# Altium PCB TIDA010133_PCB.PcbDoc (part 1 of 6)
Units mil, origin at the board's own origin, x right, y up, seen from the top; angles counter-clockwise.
Board outline 4100 x 6400 mil, 8 copper layers (Top Layer, Ground 1, Signal 1, Power 1, Ground 2, Signal 2, Power 2, Bottom Layer), stack 60.4 mil thick; 587 components, 322 nets, 1661 pads, 859 vias.
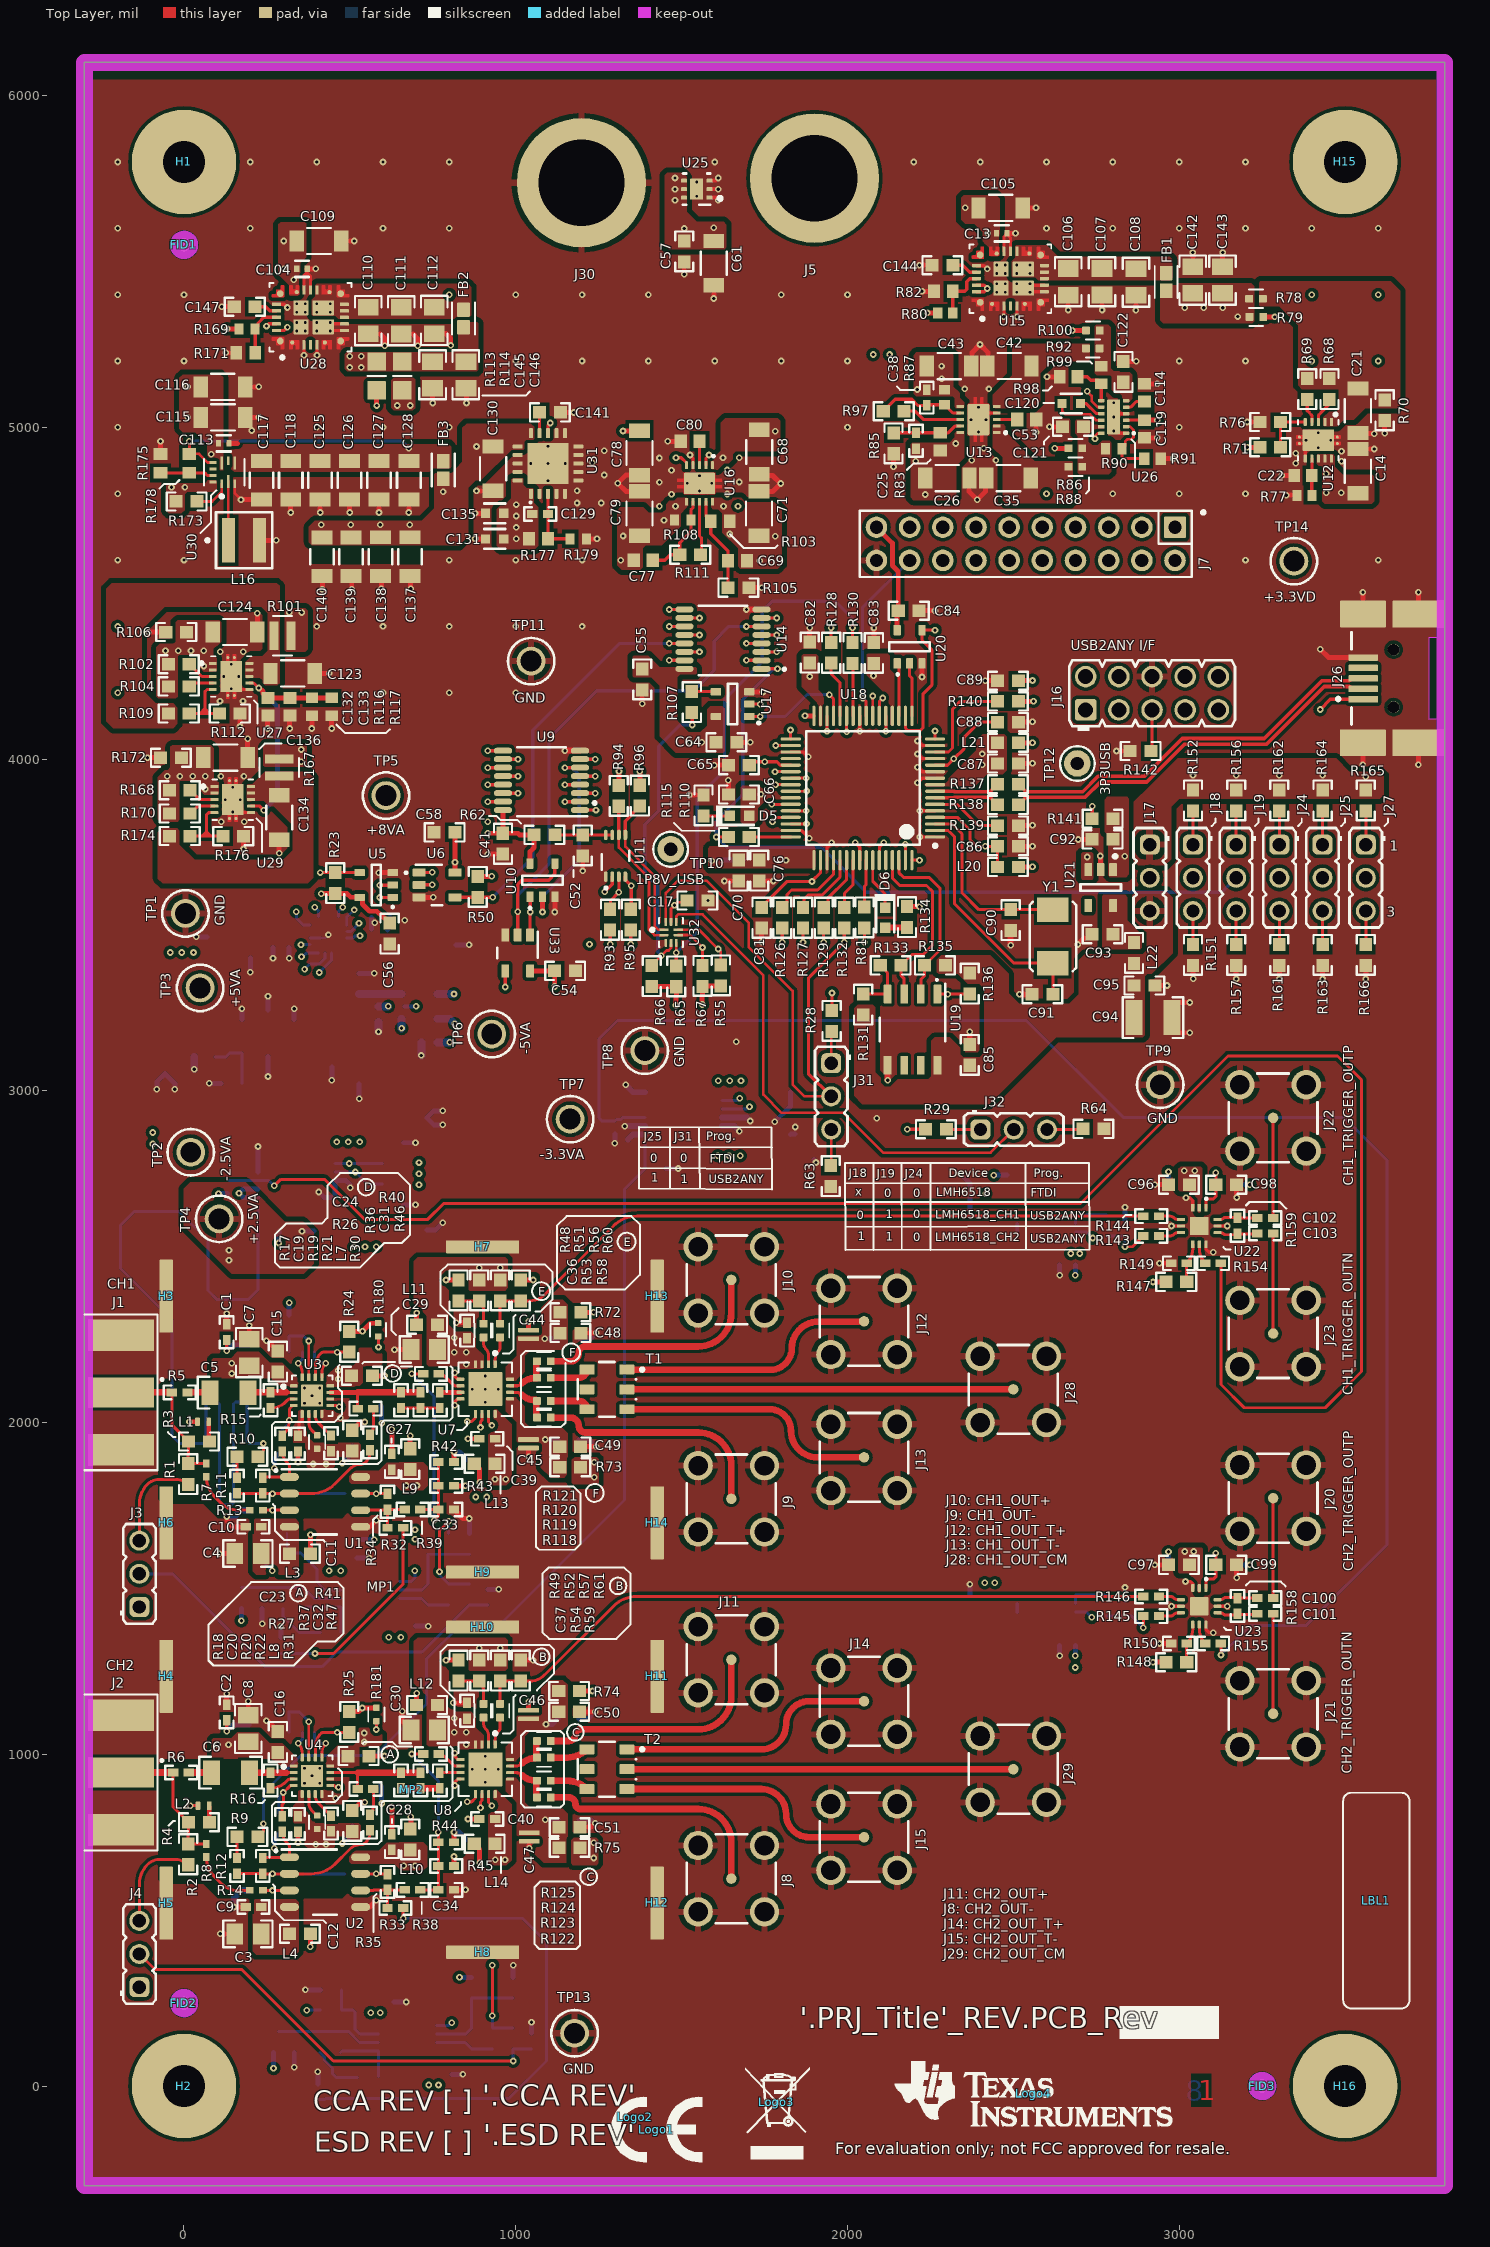
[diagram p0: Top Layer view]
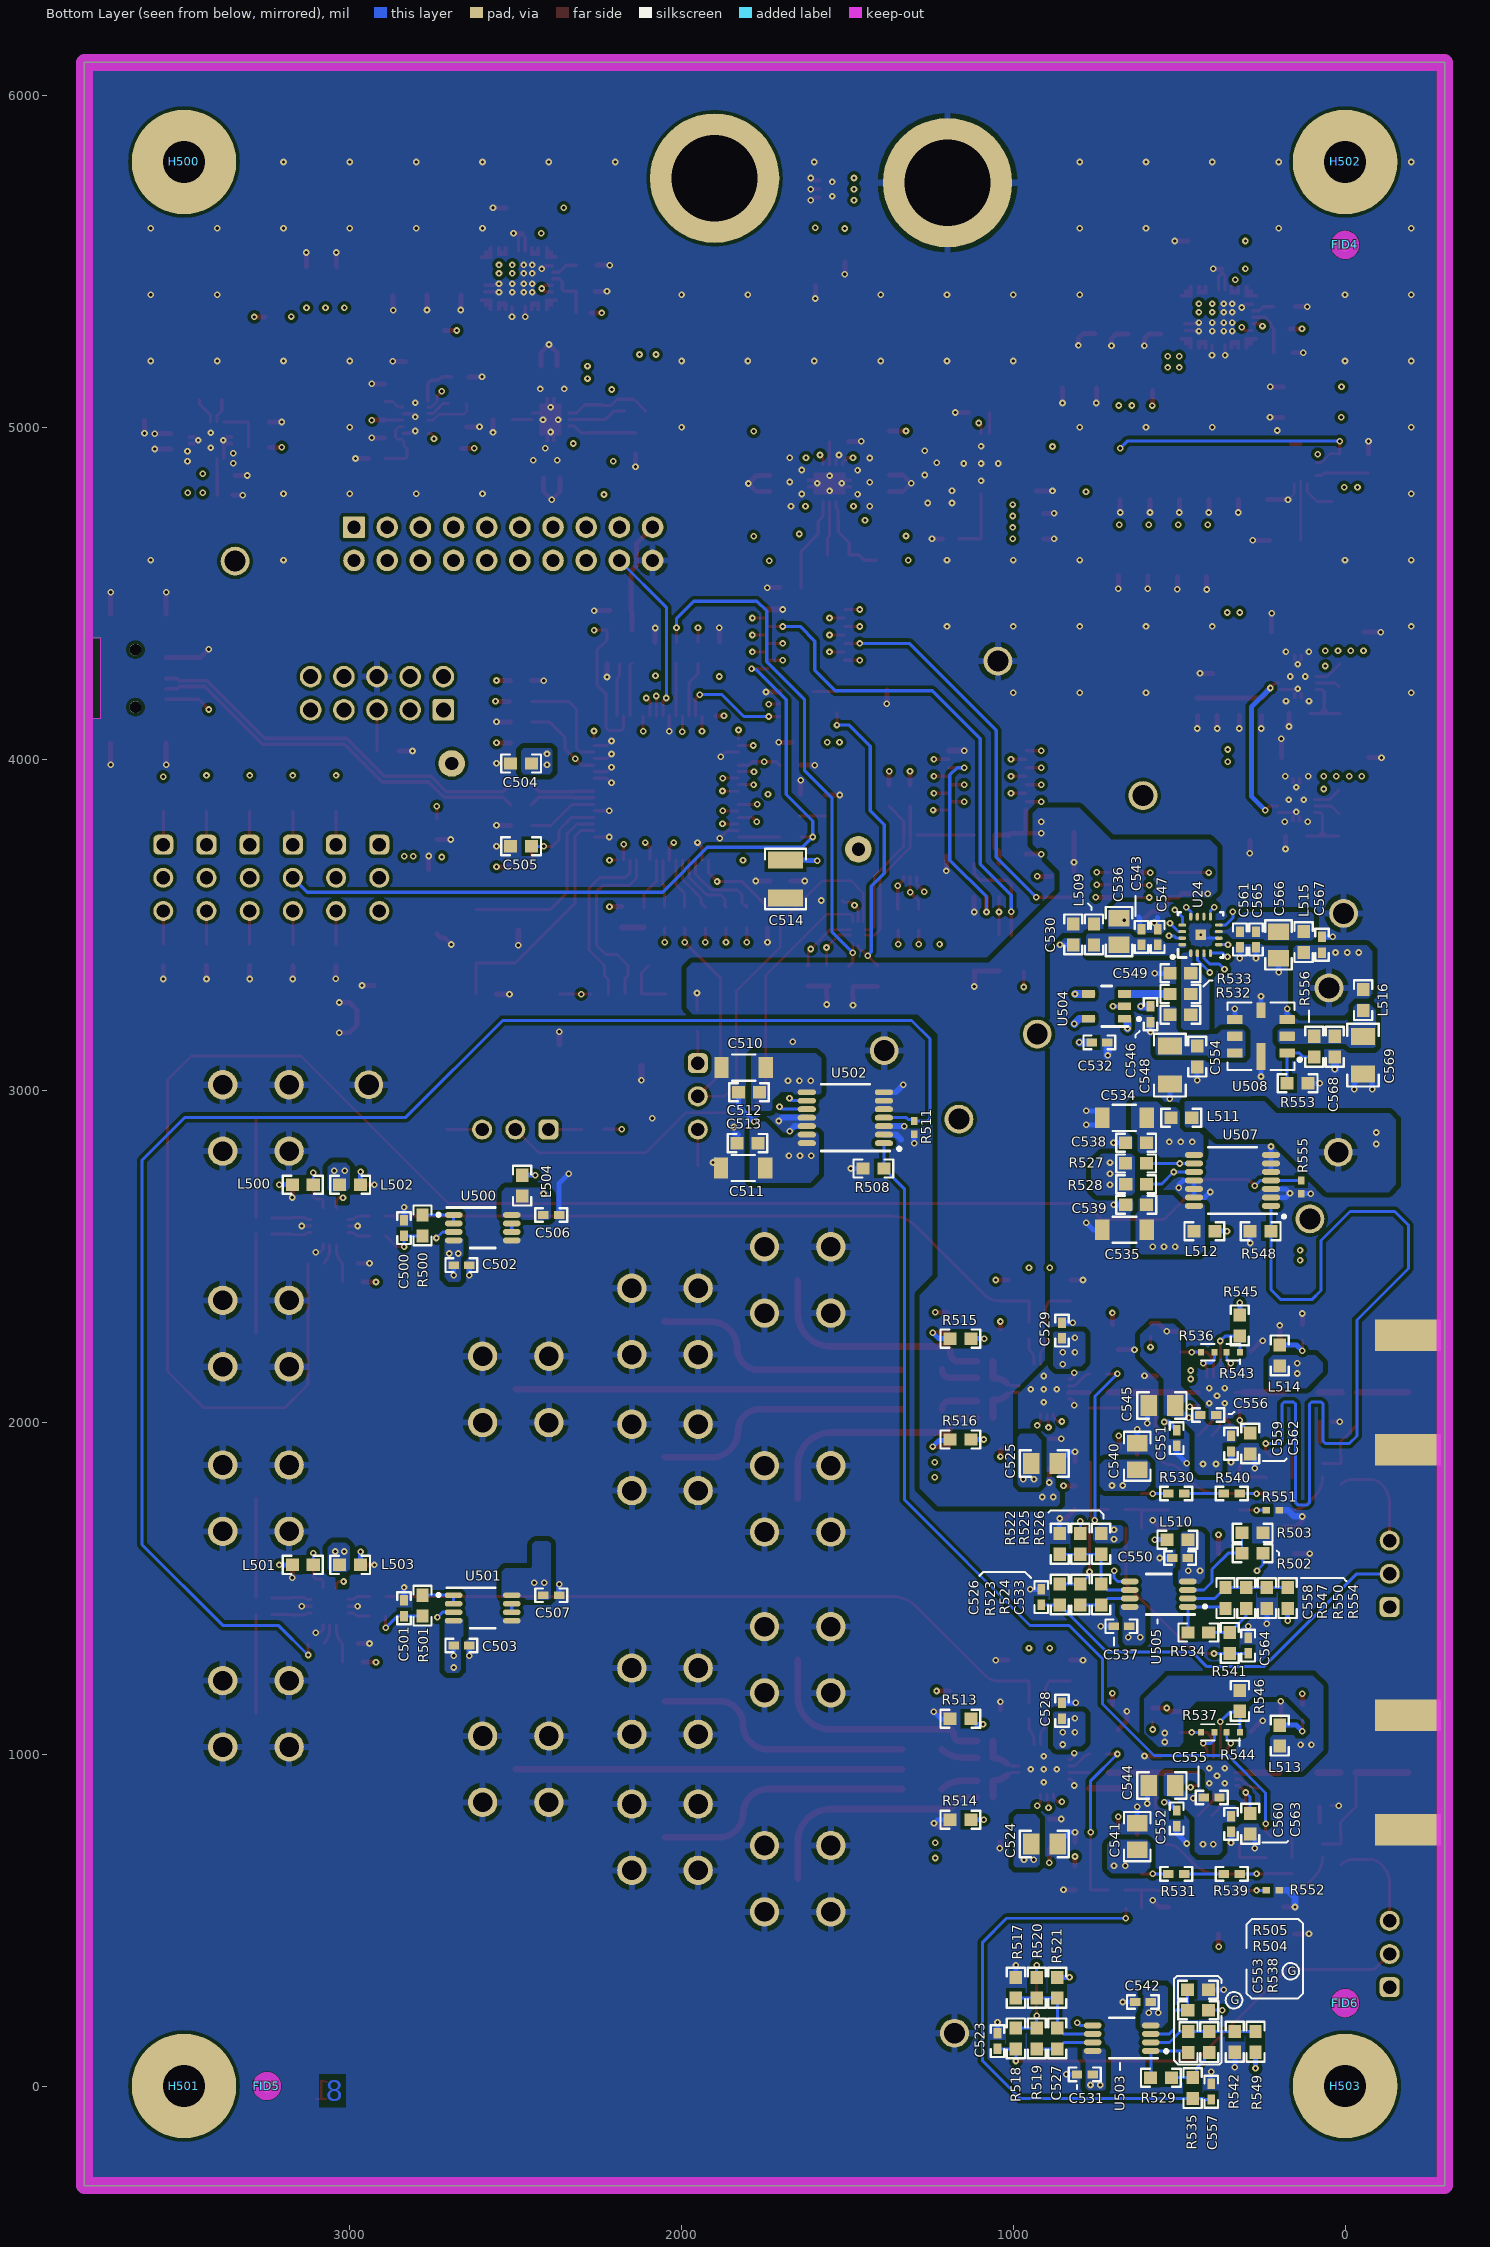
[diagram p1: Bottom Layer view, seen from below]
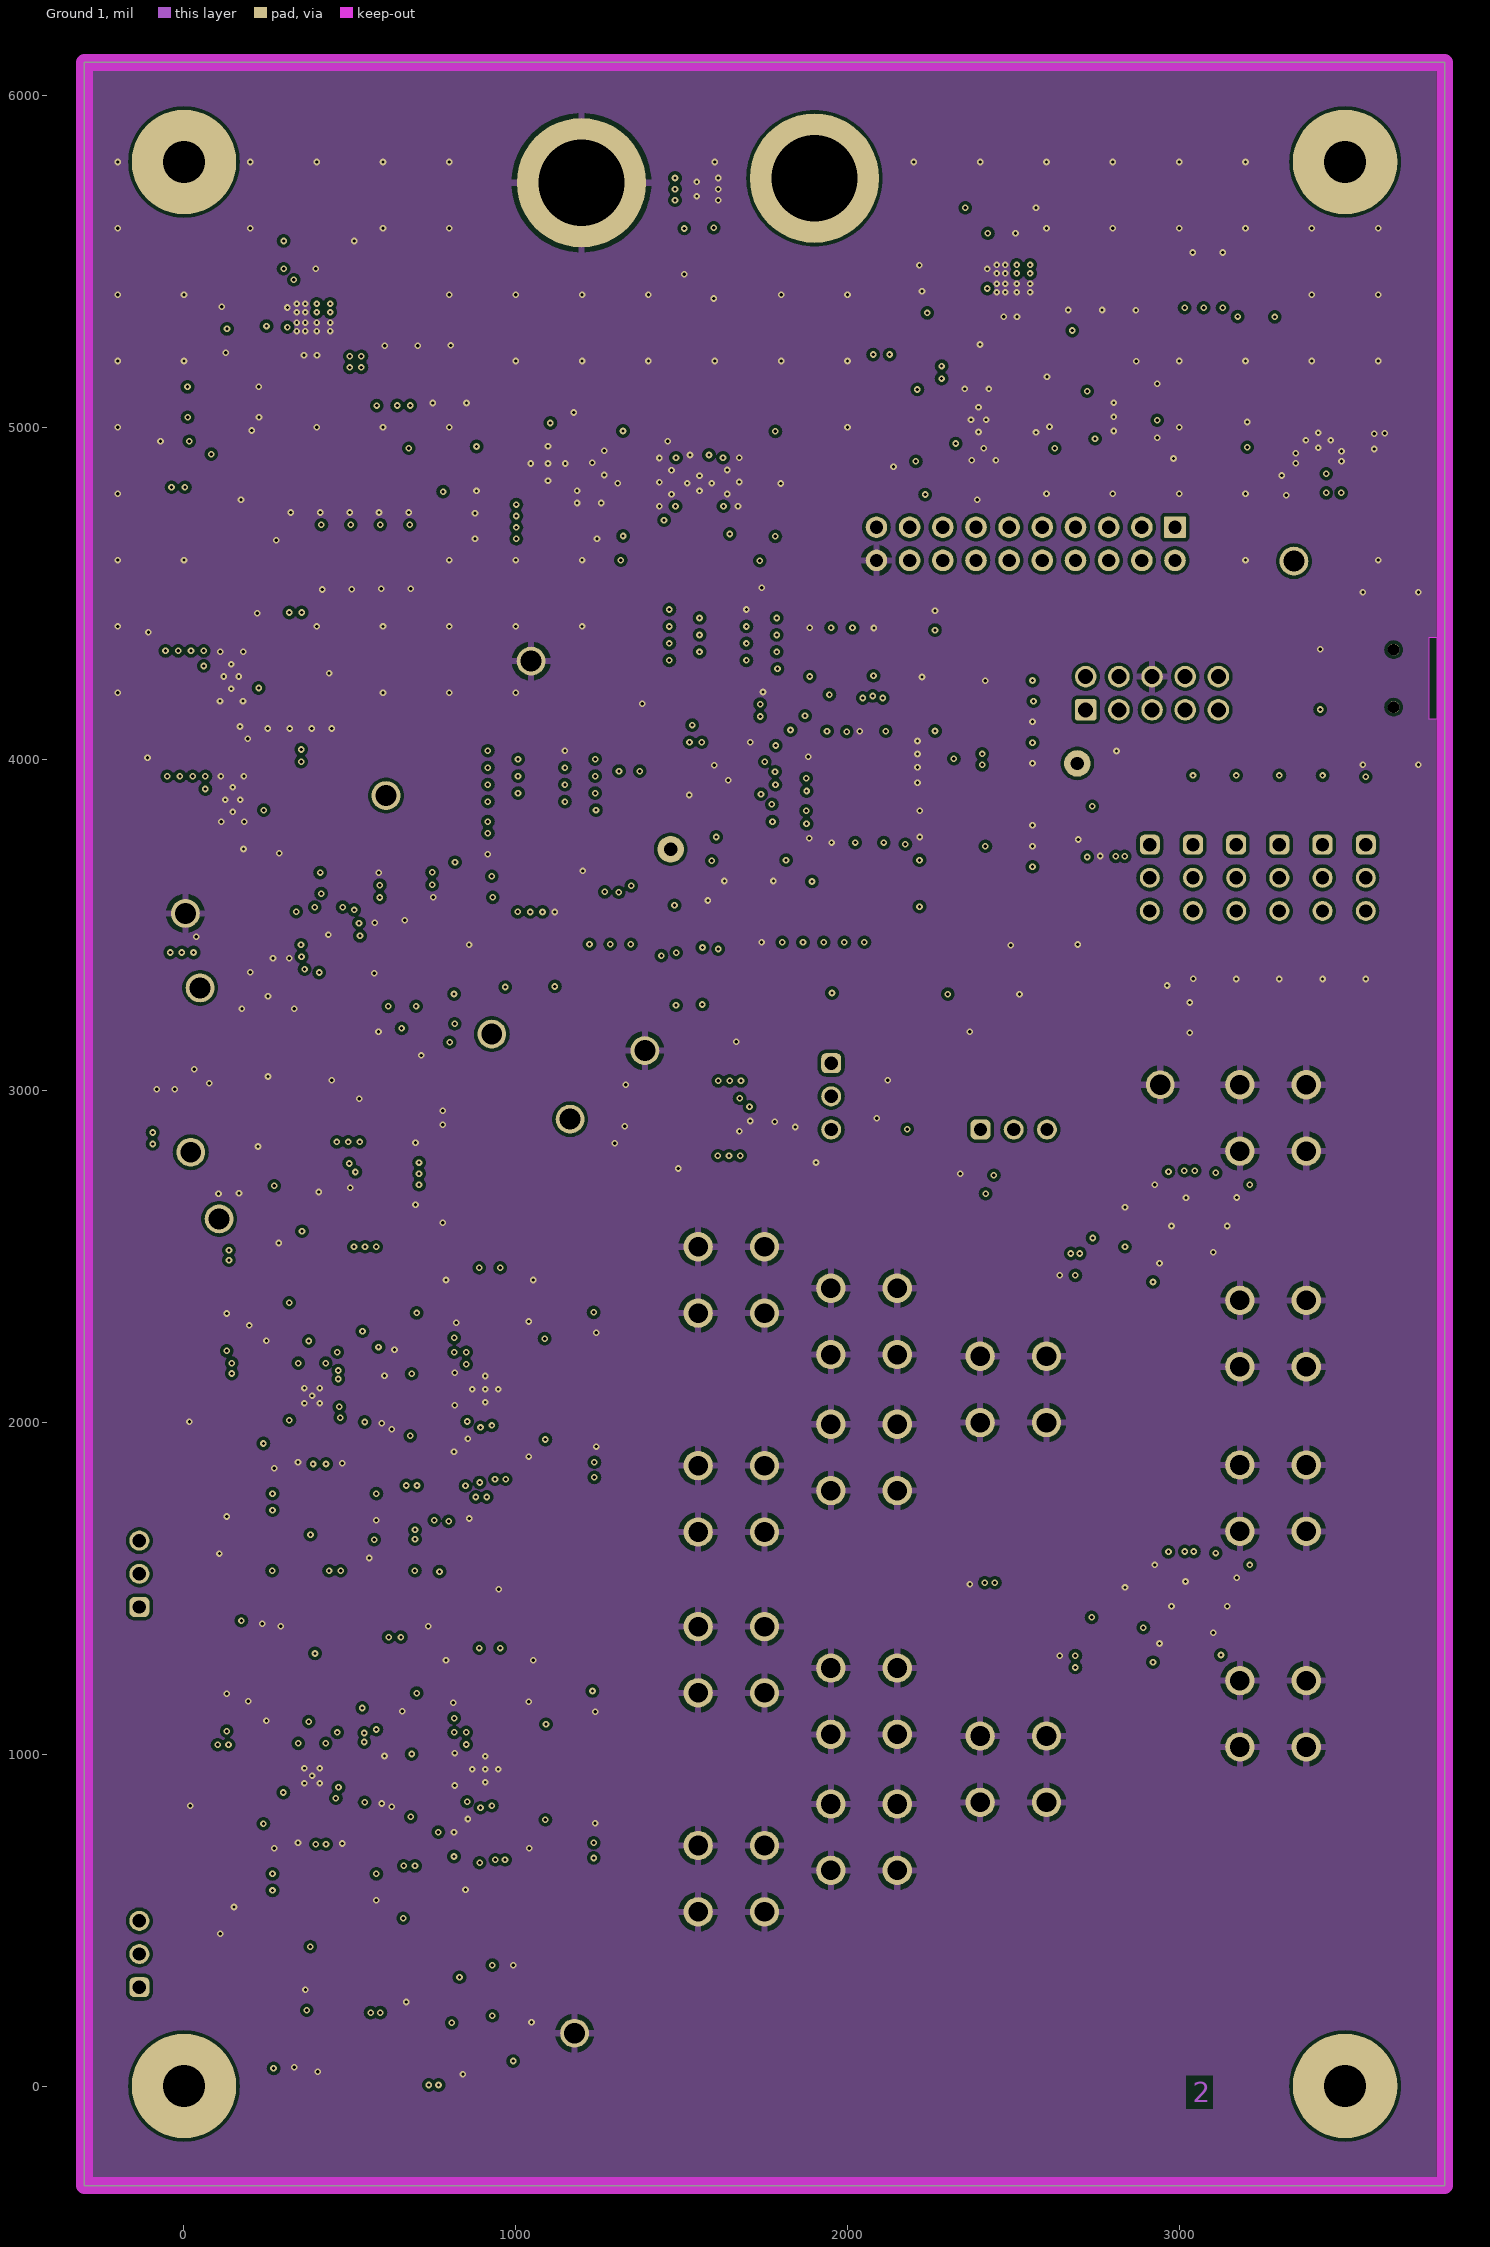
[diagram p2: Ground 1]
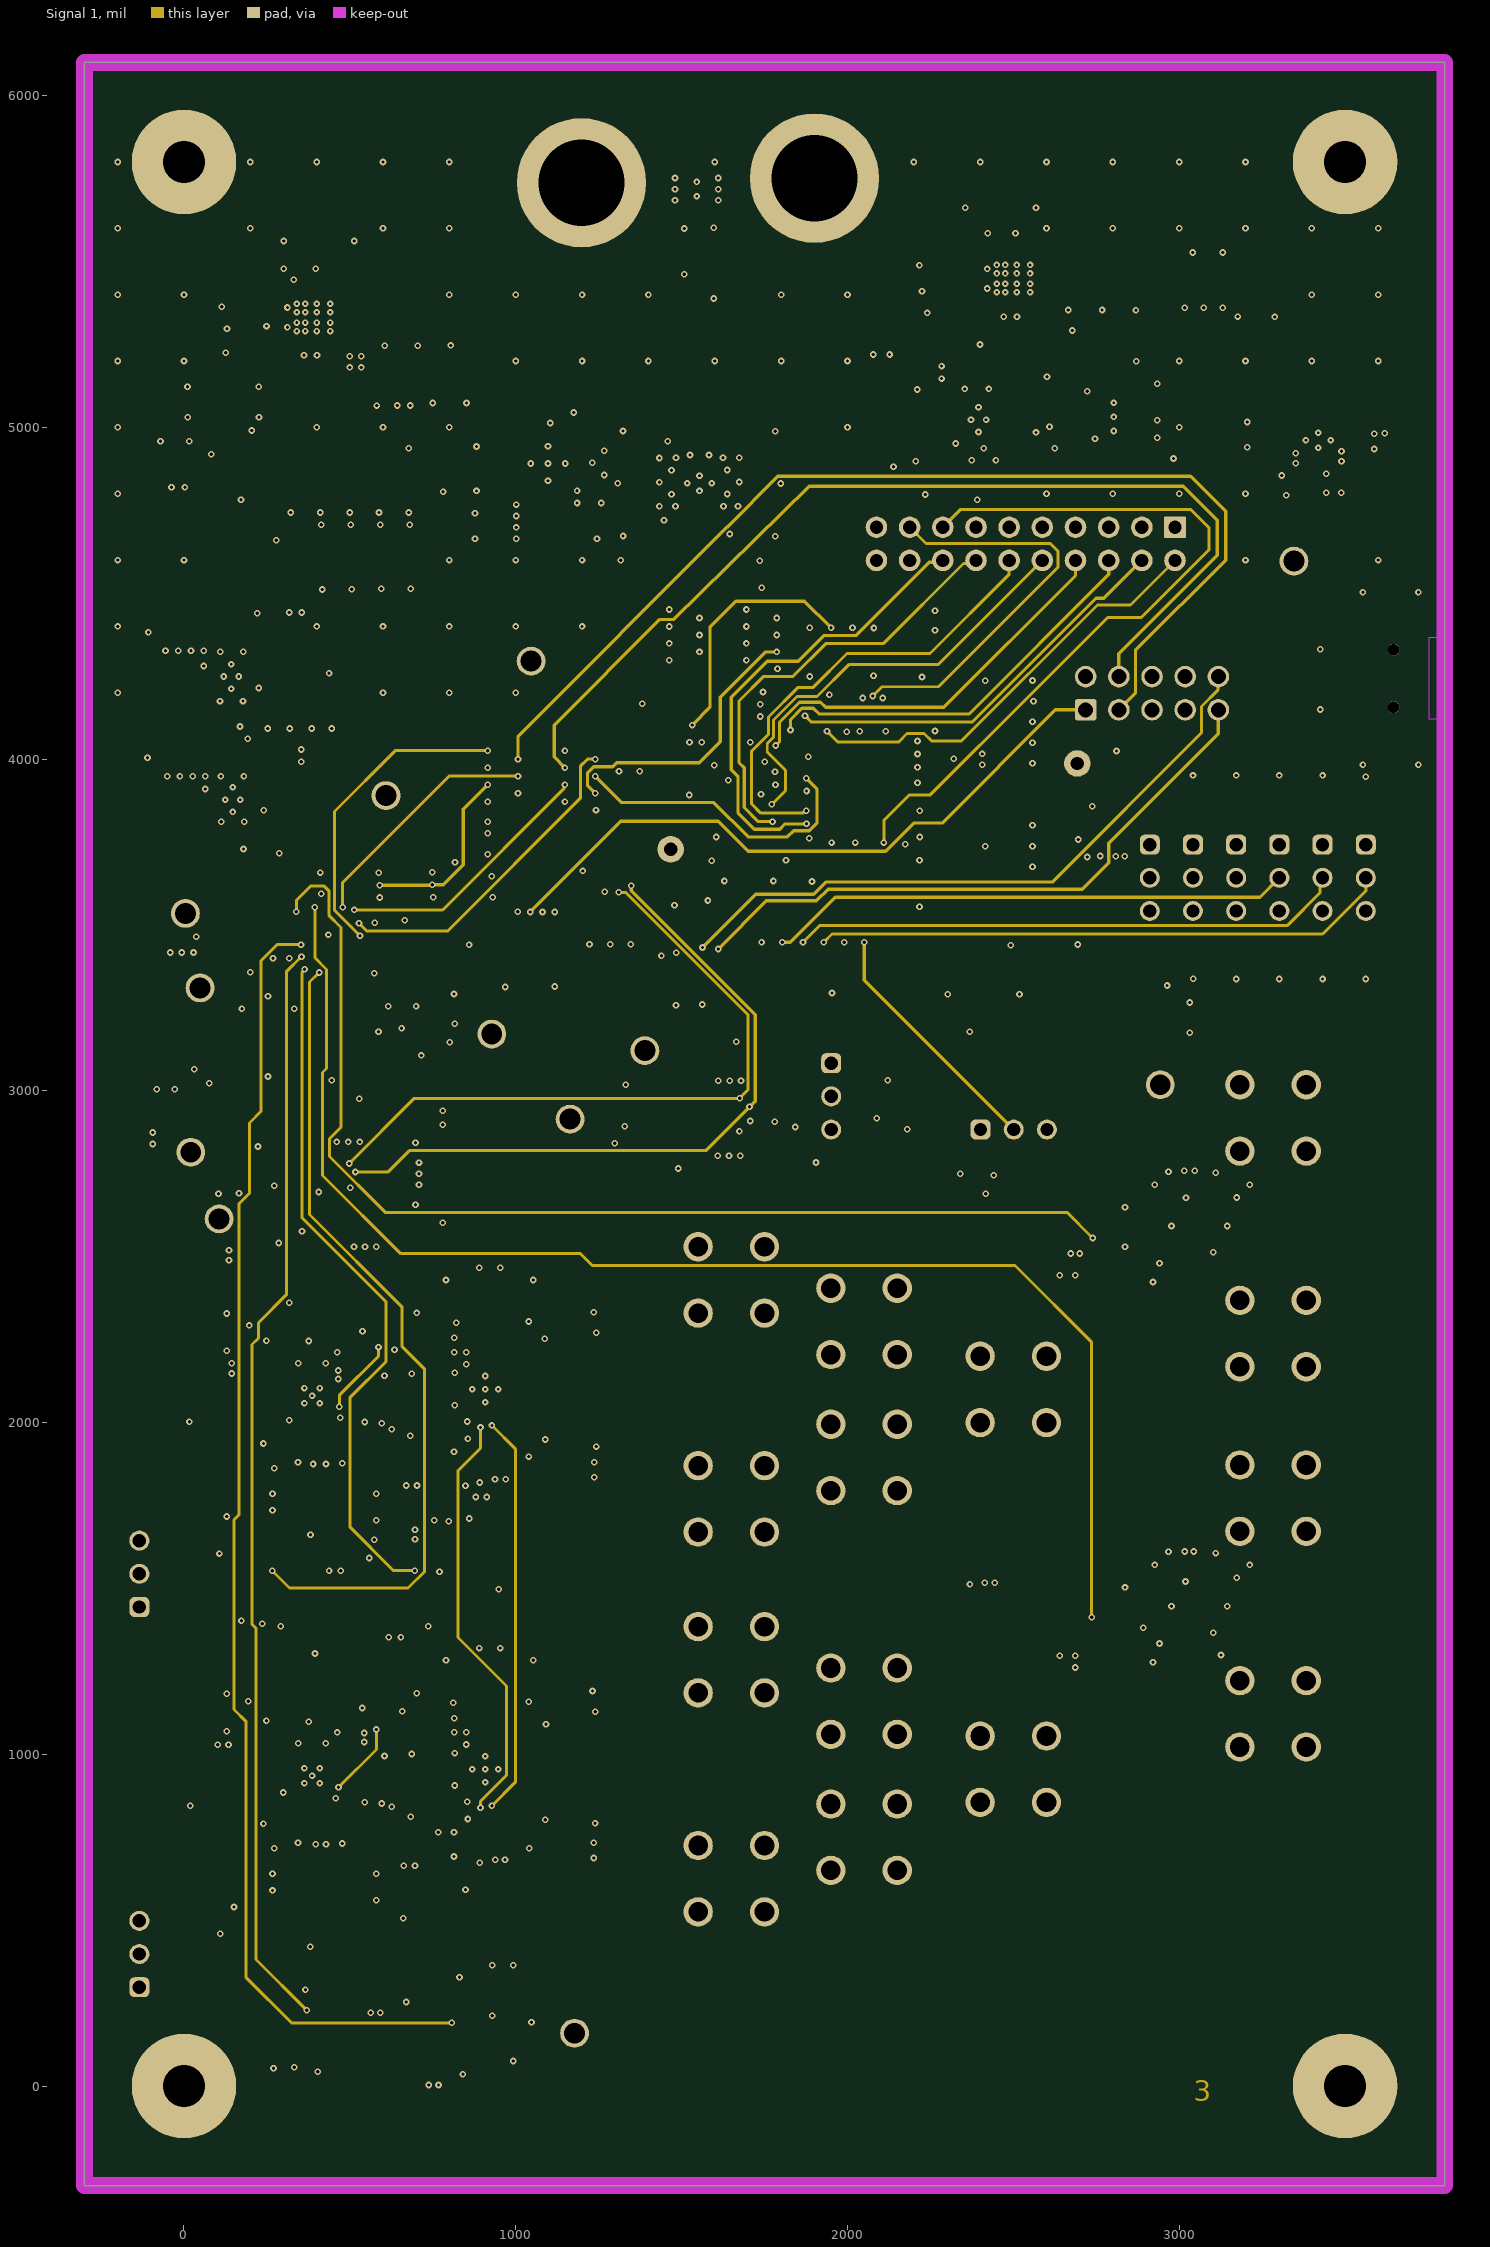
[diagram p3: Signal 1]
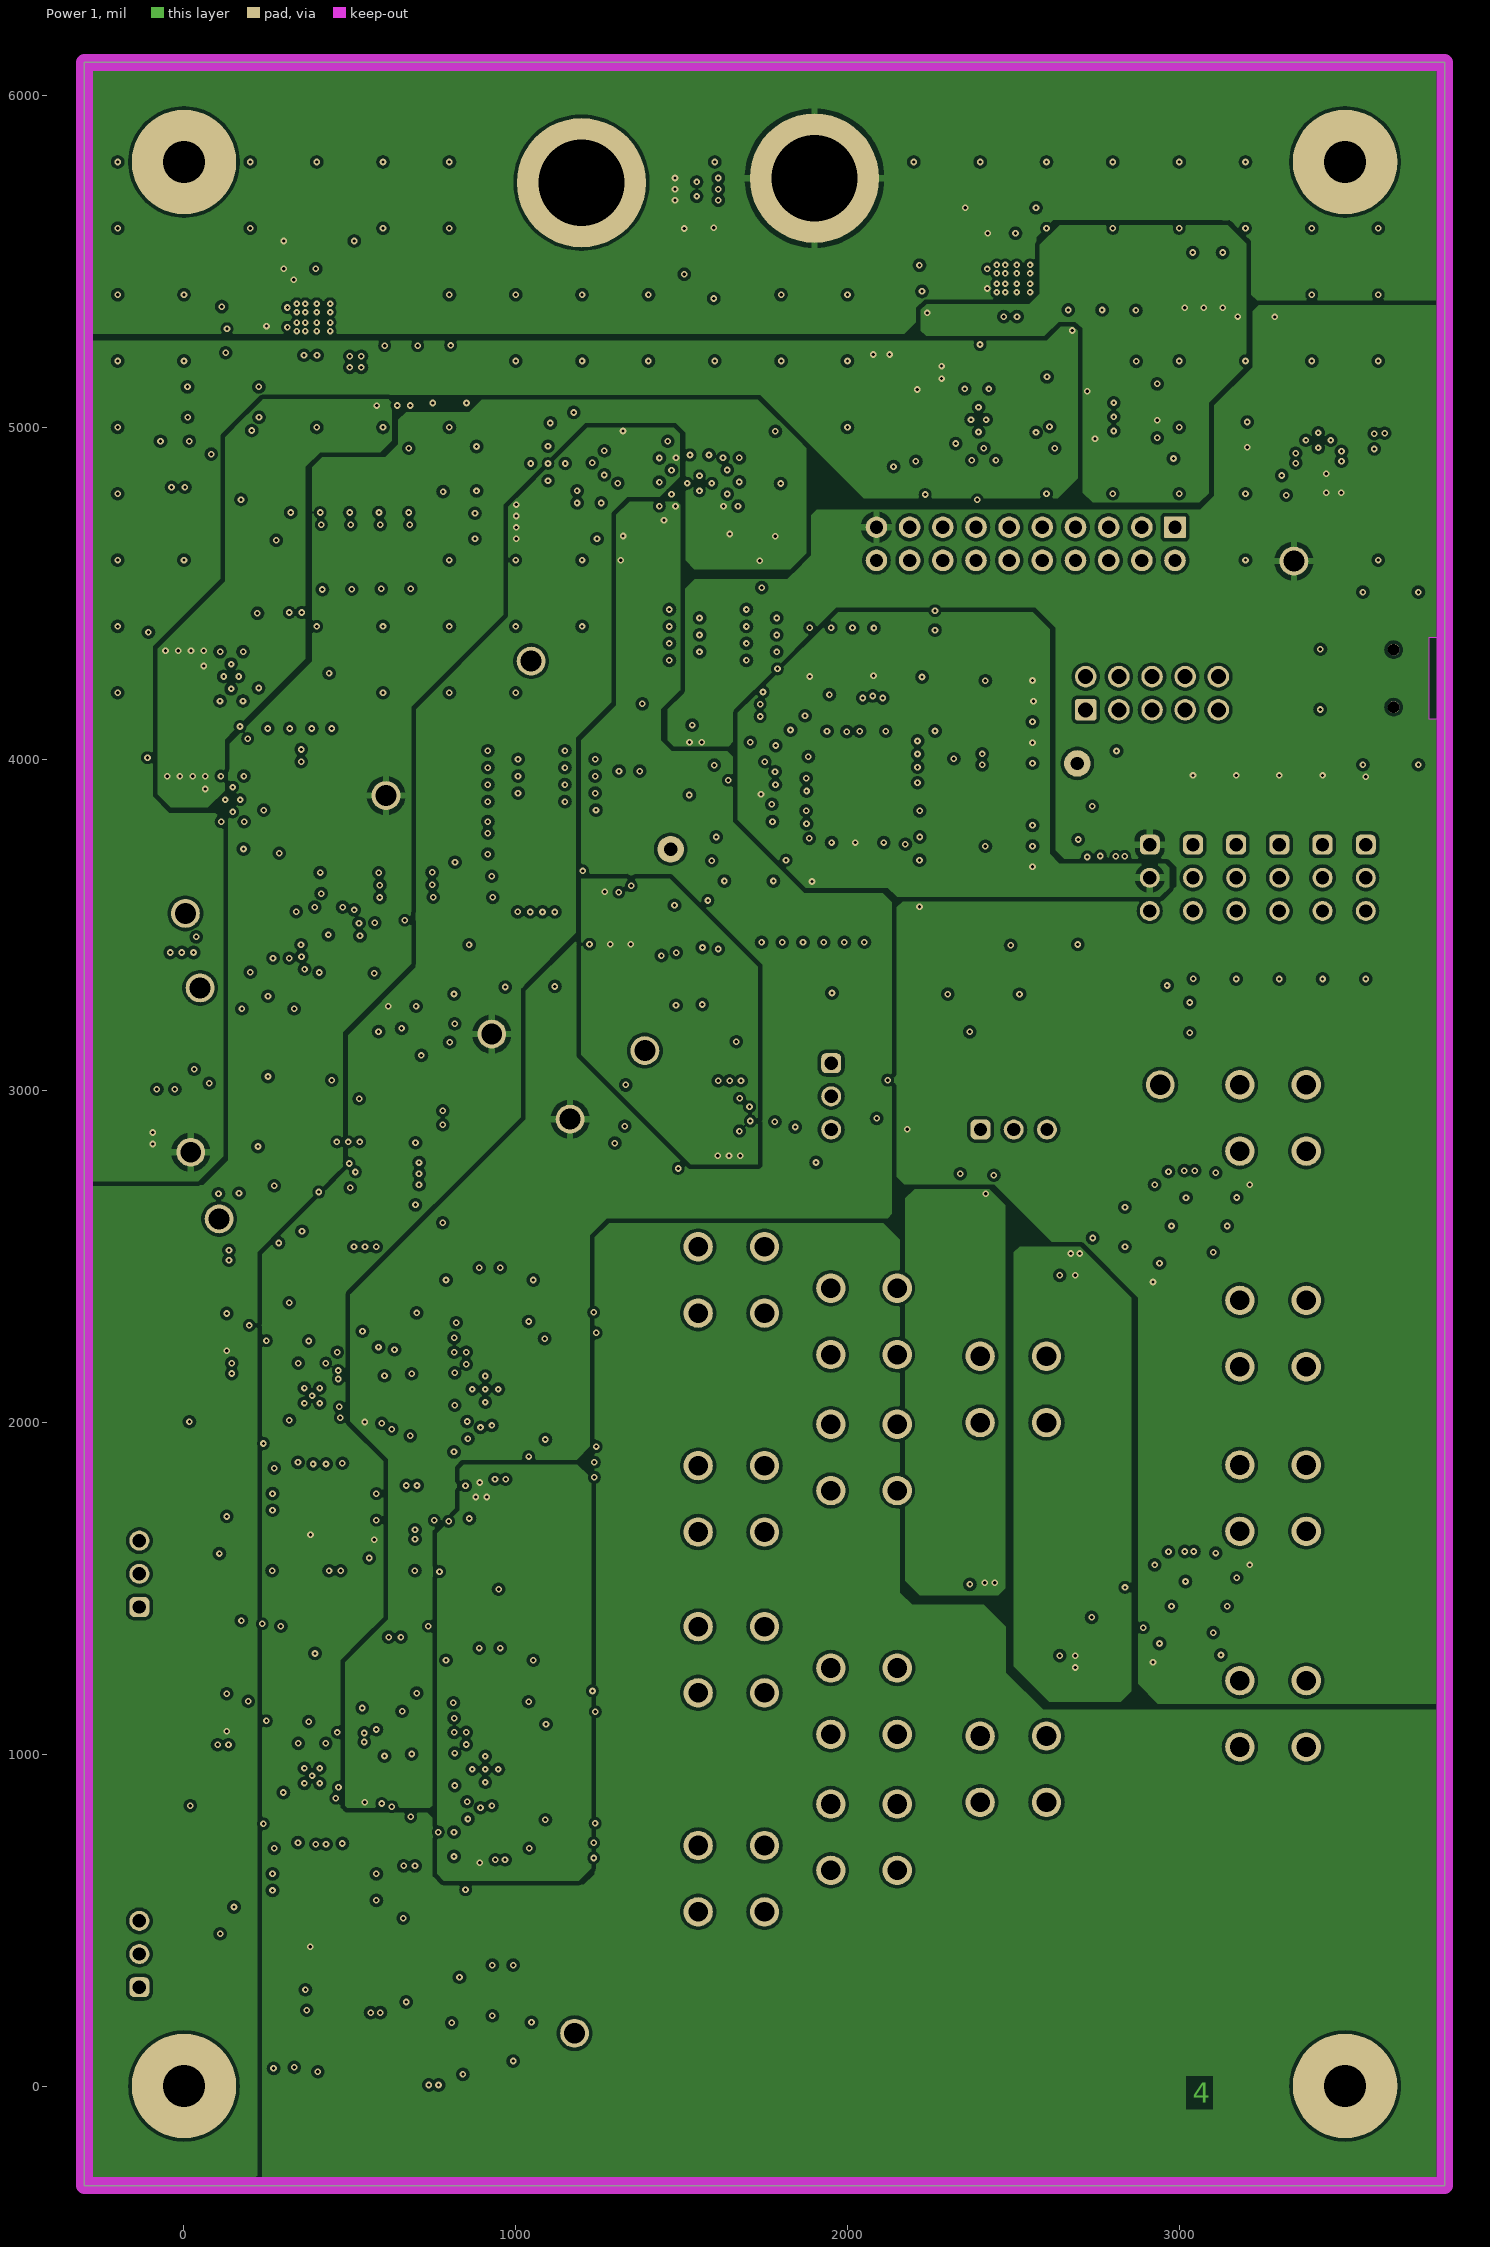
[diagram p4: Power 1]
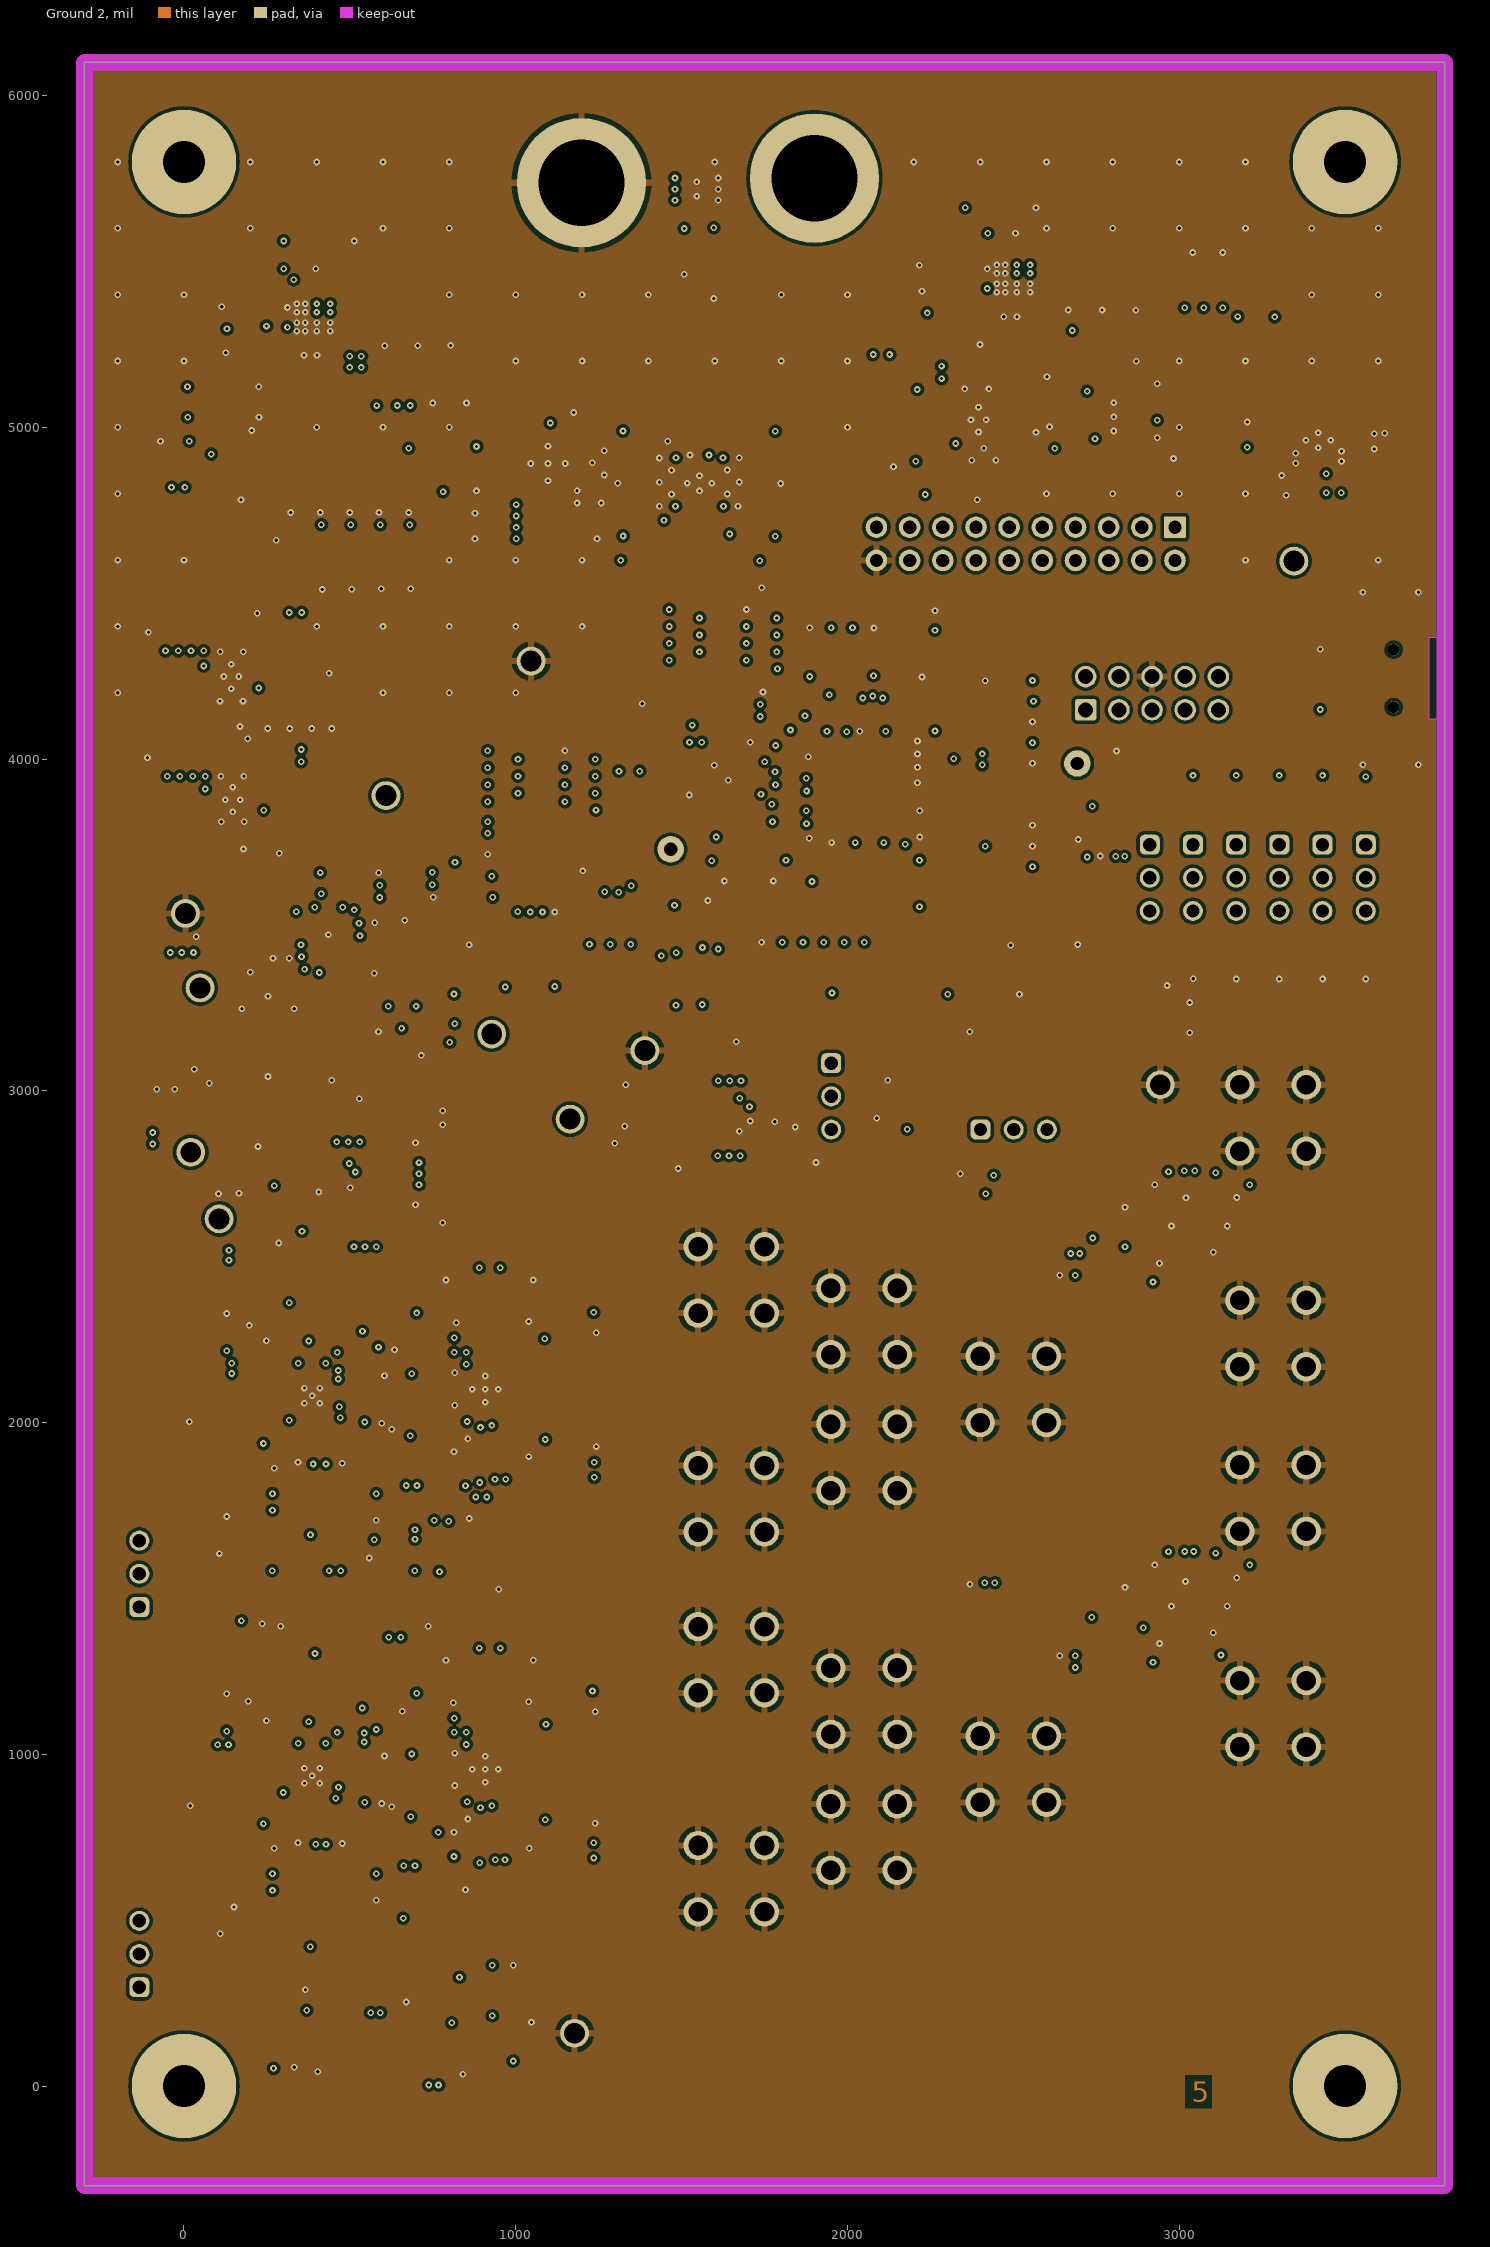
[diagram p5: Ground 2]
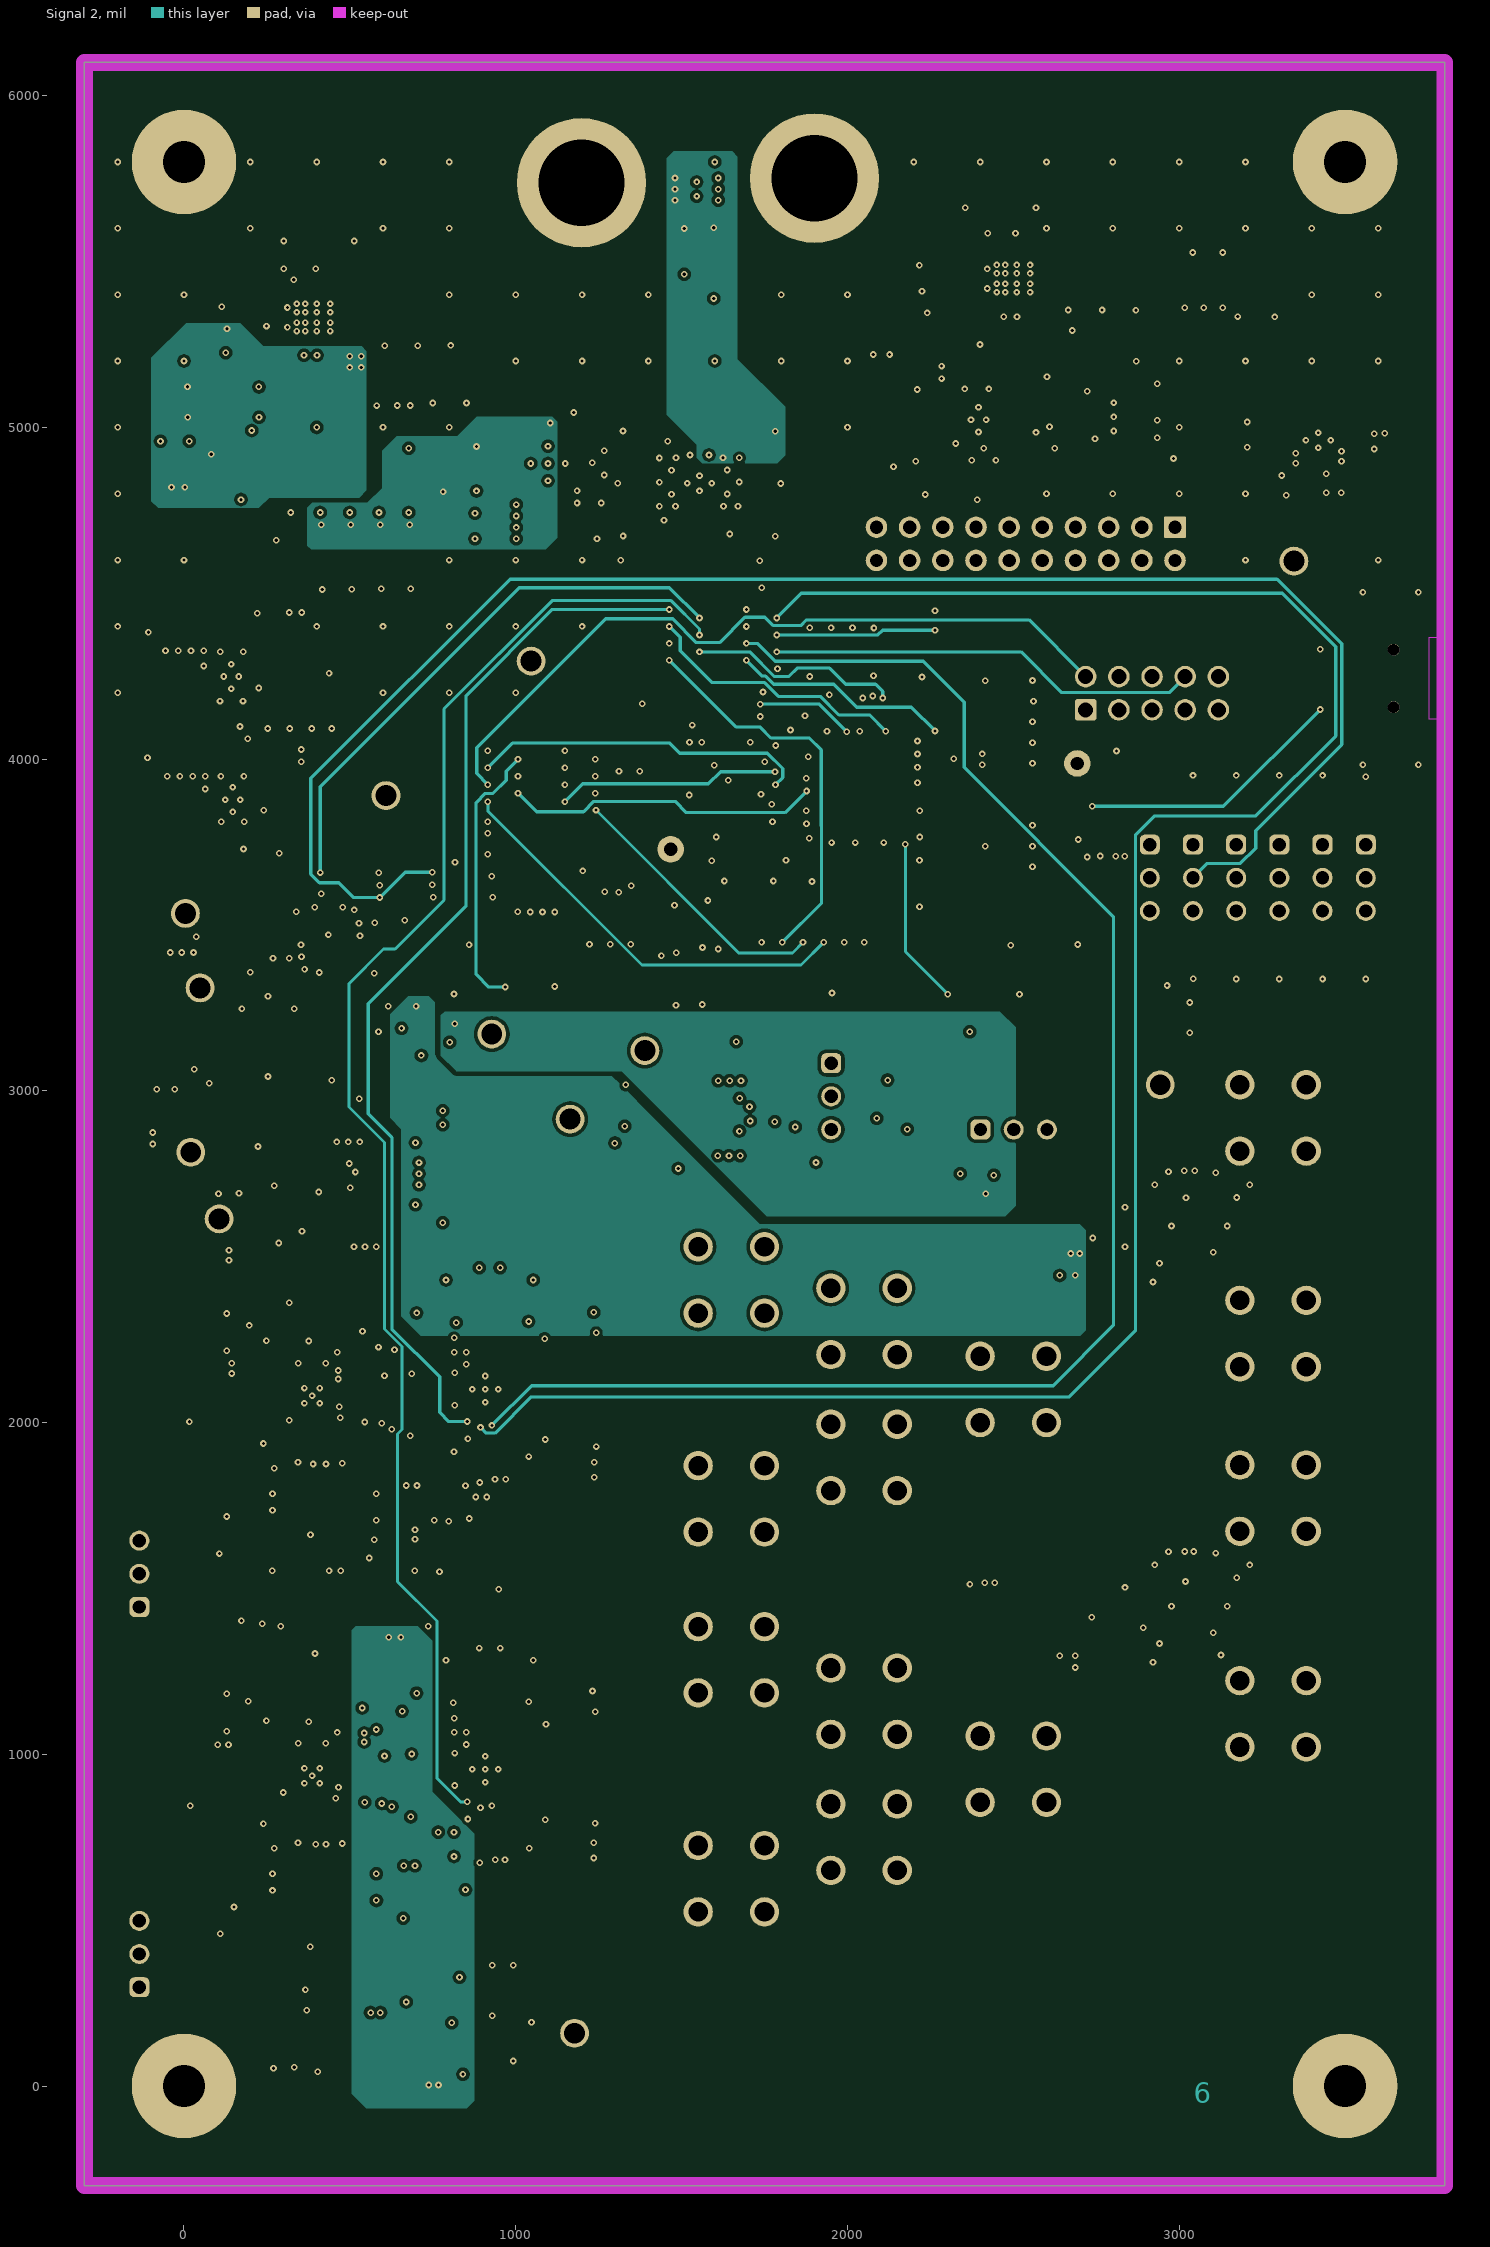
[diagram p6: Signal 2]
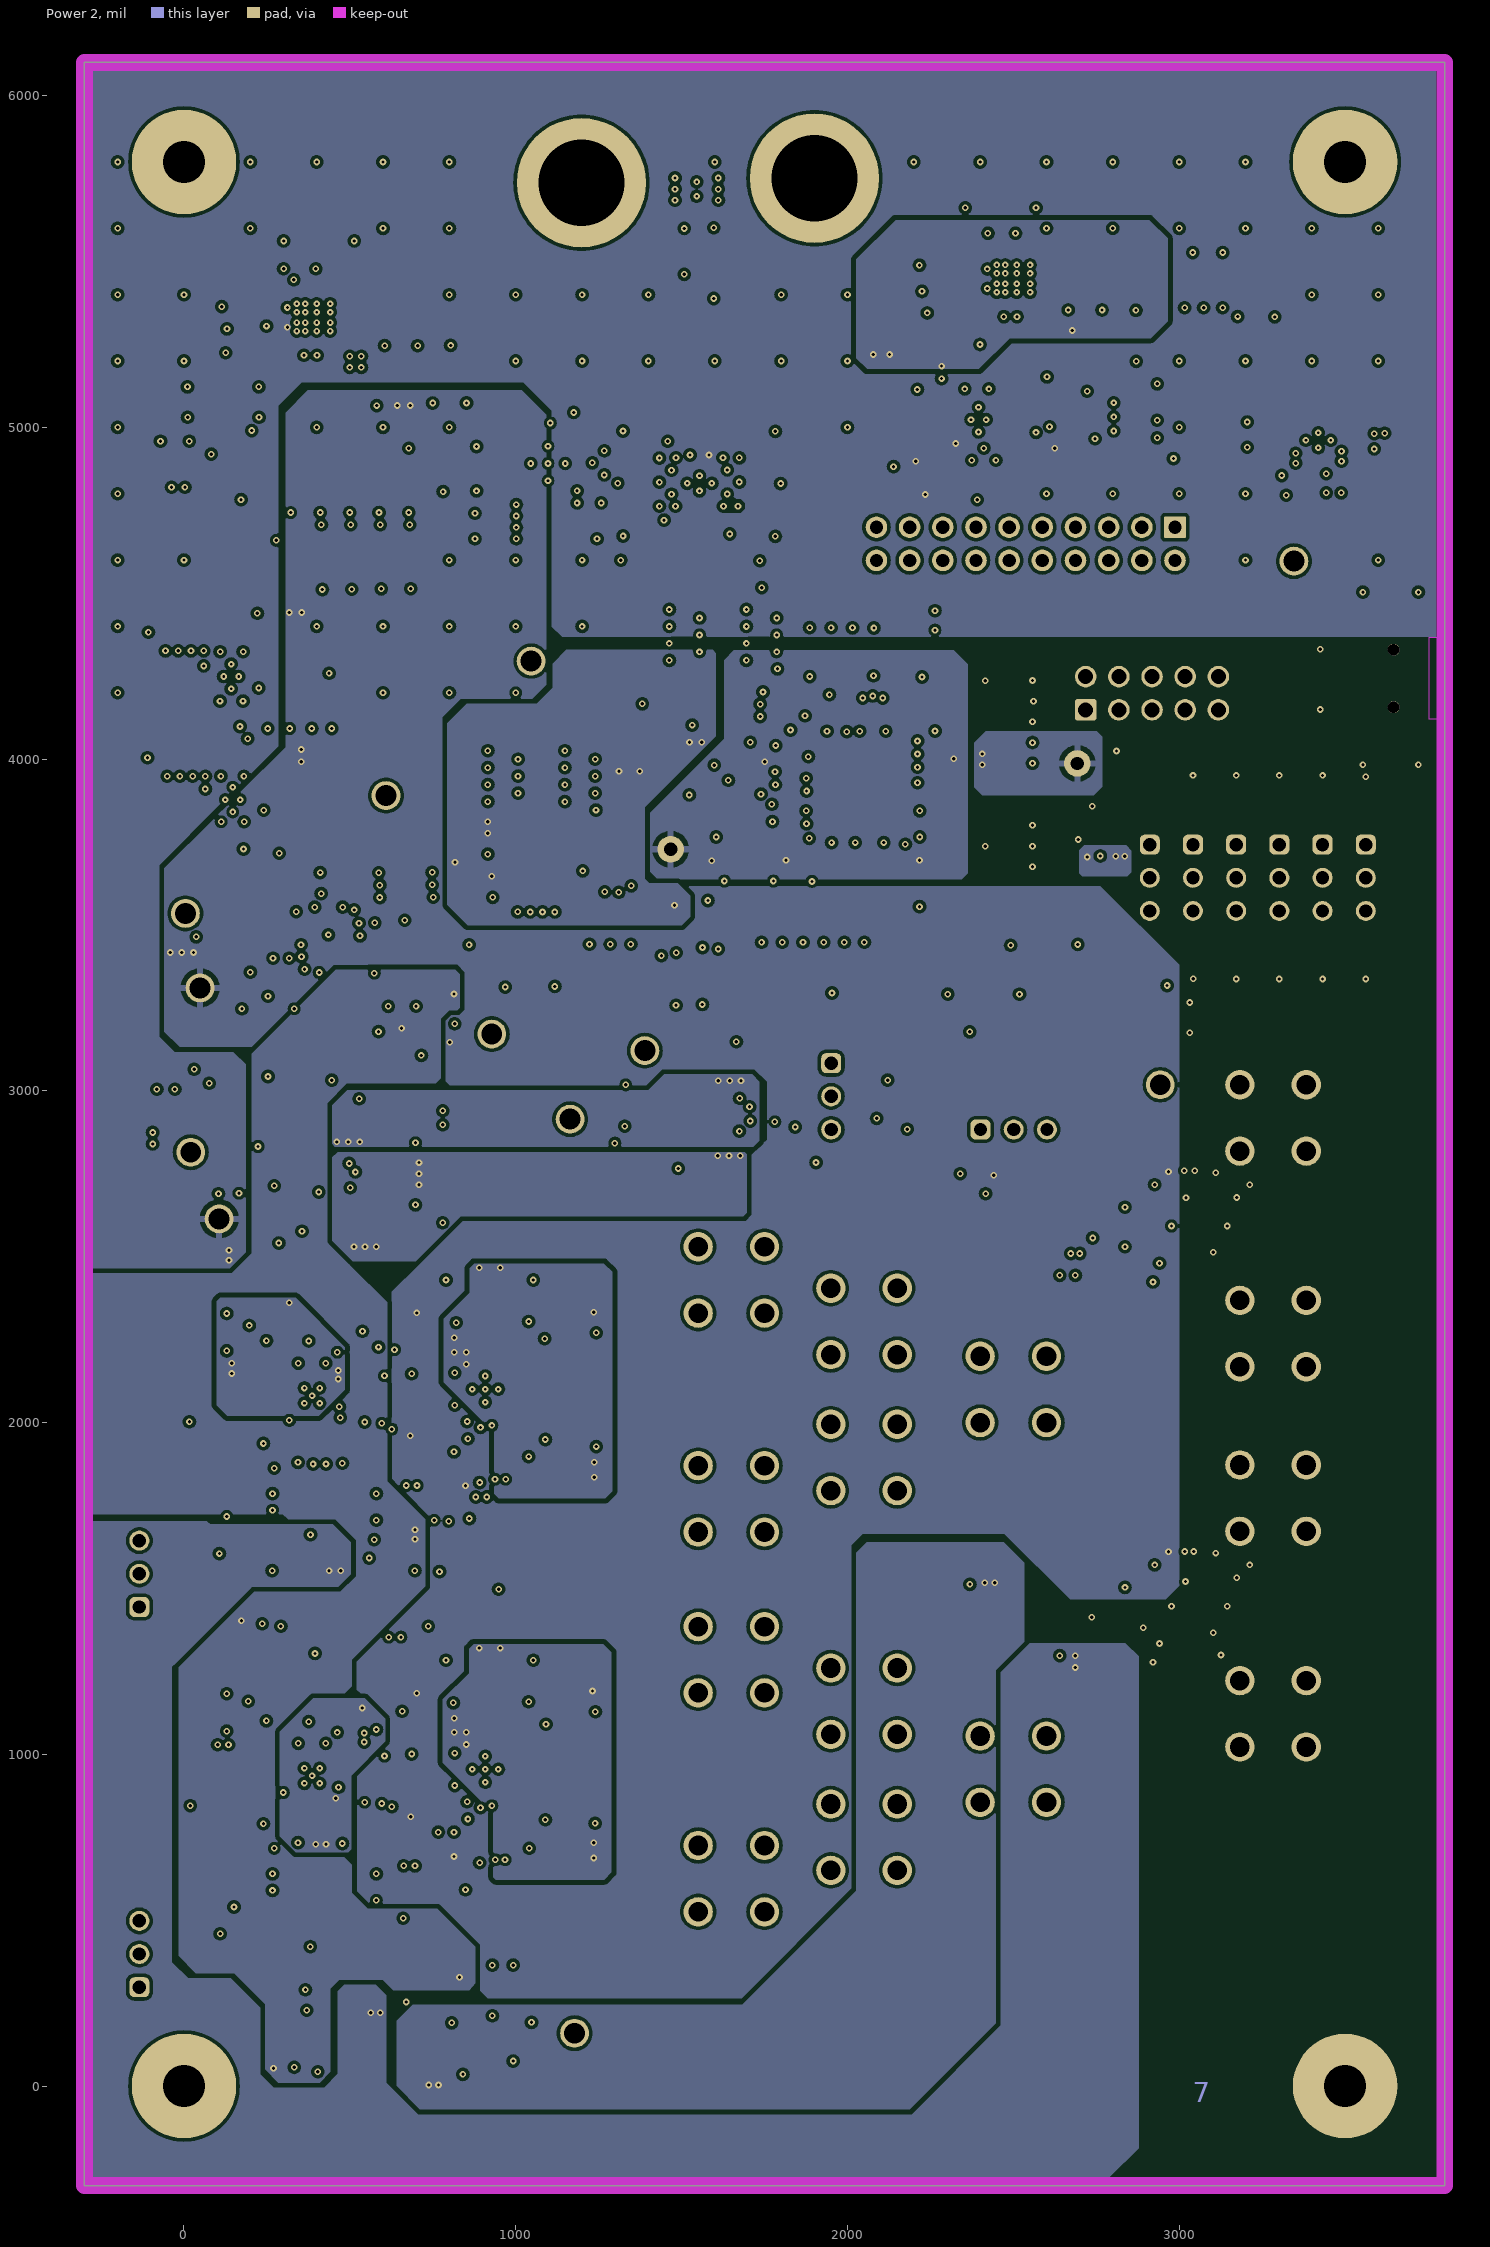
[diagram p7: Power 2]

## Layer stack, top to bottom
Top Solder: solder mask 0.8, Solder Resist, Dk 3.5
Top Layer: signal copper 2.1
Dielectric 1: core 11, FR-4, Dk 4.2
Ground 1: signal copper 1.4
Dielectric 2: dielectric 5, FR-4, Dk 4.2
Signal 1: signal copper 1.4
Dielectric 3: prepreg 5, FR-4, Dk 4.2
Power 1: signal copper 1.4
Dielectric 4: prepreg 5.8, FR-4, Dk 4.2
Ground 2: signal copper 1.4
Dielectric 5: prepreg 5, FR-4, Dk 4.2
Signal 2: signal copper 1.4
Dielectric 6: dielectric 5, FR-4, Dk 4.2
Power 2: signal copper 1.4
Dielectric 7: core 11, FR-4, Dk 4.2
Bottom Layer: signal copper 2.1
Bottom Solder: solder mask 0.8, Solder Resist, Dk 3.5

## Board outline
-300,-300 3800,-300 3800,6100 -300,6100

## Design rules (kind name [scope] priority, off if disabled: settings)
AcuteAngle [All] p1: minimum=4.50000000000000E+0001 checktracksonly=FALSE
AssemblyTestPointUsage [All] p1: valid=2
BoardOutlineClearance BoardOutlineClearance_MountingHoles [OnCopper and InComponentClass('Mounting Holes')] p1: gap=40 ignorepadtopadclearanceinfootprint=FALSE
BoardOutlineClearance BoardOutlineClearance_Poly [OnCopper and IsPoly] p2: gap=25 ignorepadtopadclearanceinfootprint=FALSE
Clearance Clearance_FiducialMark [IsKeepOut and InComponentClass('FiducialMark') vs IsPad and InComponentClass('FiducialMark')] p1: gap=0 ignorepadtopadclearanceinfootprint=FALSE
Clearance Clearance_Keepouts [IsKeepOut] p2: gap=1 ignorepadtopadclearanceinfootprint=FALSE
Clearance Clearance_PolytoPloy [InPolygon vs InPolygon] p3: gap=15 ignorepadtopadclearanceinfootprint=FALSE
Clearance Clearance_Poly [InPolygon] p4: gap=10 ignorepadtopadclearanceinfootprint=FALSE
Clearance [All] p5: gap=6 ignorepadtopadclearanceinfootprint=FALSE
ComponentClearance "ComponentClearance_RF shield" [HasFootprint('FP-1.0 x 1.5 x 0.25_RF_SHIELD-MFG') vs HasFootprint('Harwin_S1721-46R')] p1: gap=0 collisioncheckmode=3 verticalgap=0 showdistances=FALSE
ComponentClearance ComponentClearance_Screw2nut [HasFootprint('NY PMS 440 0025 PH') vs HasFootprint('Keystone_1902E')] p2: gap=5 collisioncheckmode=3 verticalgap=10 showdistances=FALSE
ComponentClearance [All] p3: gap=10 collisioncheckmode=3 verticalgap=10 showdistances=FALSE
DiffPairsRouting [All] p1: maxlimit=6 minlimit=6 mostfreqgap=6 toplayer_minwidth=9.84 toplayer_maxwidth=11 toplayer_prefwidth=11 midlayer1_minwidth=9.84 midlayer1_maxwidth=11 midlayer1_prefwidth=11 midlayer2_minwidth=9.84 midlayer2_maxwidth=11 midlayer2_prefwidth=11 midlayer3_minwidth=9.84 midlayer3_maxwidth=11 midlayer3_prefwidth=11 midlayer4_minwidth=9.84 midlayer4_maxwidth=11 midlayer4_prefwidth=11 midlayer5_minwidth=9.84 midlayer5_maxwidth=11 midlayer5_prefwidth=11 midlayer6_minwidth=9.84 midlayer6_maxwidth=11 midlayer6_prefwidth=11 bottomlayer_minwidth=9.84 bottomlayer_maxwidth=11 bottomlayer_prefwidth=11 maxuncoupledlength=1000
FabricationTestPointUsage TestPointUsage [All] p1: valid=2 allowmultiple=FALSE
FabricationTestpoint Testpoint [All] p1: side=3 testpointundercomponent=TRUE minsize=40 maxsize=100 preferedsize=60 minholesize=0 maxholesize=40 preferedholesize=32 testpointgrid=1 allowsidetop=TRUE allowsidebottom=TRUE usegrid=TRUE gridtolerance=0.01
FanoutControl Fanout_LCC [IsLCC] p1: bgadir=Out bgaviamode=Centered fanoutstyle=Auto fanoutdirection=Alternating viagrid=1 // Fanout_LCC (Default Rule)
FanoutControl Fanout_BGA [IsBGA] p2: bgadir=Out bgaviamode=Centered fanoutstyle=Auto fanoutdirection=Alternating viagrid=1 // Fanout_BGA (Default Rule)
FanoutControl Fanout_Default [All] p4: bgadir=Out bgaviamode=Centered fanoutstyle=Auto fanoutdirection=Alternating viagrid=1 // Fanout_Default (Default Rule)
FanoutControl Fanout_Small [(CompPinCount < 5)] p5: bgadir=Out bgaviamode=Centered fanoutstyle=Auto fanoutdirection=OutThenIn viagrid=1 // Fanout_Small (Default Rule)
Height [All] p1: minheight=0 maxheight=1001 prefheight=500
HoleSize [All] p1: absolutevalues=TRUE maxlimit=260 minlimit=7.87 maxpercent=80.000 minpercent=20.000
MinimumAnnularRing MinimumAnnularRing_ThermalPadVias [IsVia] p1: minimumring=5
MinimumAnnularRing [All] p2: minimumring=7.5
MinimumSolderMaskSliver MinimumSolderMaskSliver_Logo [InComponentClass('Logo') vs InComponentClass('Logo')] p1: minsoldermaskwidth=0.7
MinimumSolderMaskSliver [All] p2: minsoldermaskwidth=3
PlaneConnect [All] p1: pad.planeconnectstyle=Relief pad.reliefexpansion=10 pad.reliefentries=4 pad.reliefconductorwidth=10 pad.reliefairgap=10 via.planeconnectstyle=Direct via.reliefexpansion=10 via.reliefentries=4 via.reliefconductorwidth=10 via.reliefairgap=10
PolygonConnect [All] p1: thpad.connectstyle=Relief thpad.reliefconductorwidth=20 thpad.reliefentries=4 thpad.polygonreliefangle="90 Angle" thpad.airgapwidth=15 smdpad.connectstyle=Direct smdpad.reliefconductorwidth=10 smdpad.reliefentries=4 smdpad.polygonreliefangle="90 Angle" smdpad.airgapwidth=10 via.connectstyle=Direct via.reliefconductorwidth=10 via.reliefentries=4 via.polygonreliefangle="90 Angle" via.airgapwidth=10
RoutingVias ThermalPadVias [IsVia and InAnyComponent] p1: holewidth=7.87 width=19.68 viastyle="Through Hole" minholewidth=7.87 minwidth=19.68 maxholewidth=12.99 maxwidth=23.62
RoutingVias [All] p2: holewidth=12 width=24 viastyle="Through Hole" minholewidth=10 minwidth=20 maxholewidth=40 maxwidth=65
SilkToBoardRegionClearance [Not ((IsComment or IsDesignator) And (Hide <> 'False')) and not InRegion(1000,500,4000,800)] p1:
SilkToSilkClearance SilkToSilkClearance_Pb-FreeLogo [(HasFootprint('Pb-Free_Overlay_Medium') OR HasFootprint('Pb-Free_Overlay_Small')) vs (HasFootprint('Pb-Free_Overlay_Medium') OR HasFootprint('Pb-Free_Overlay_Small'))] p1: silktosilkclearance=0
SilkToSilkClearance [All] p2: silktosilkclearance=4
SilkToSolderMaskClearance SilkToComponentPadClearance [(IsPad or IsFill or IsRegion) and InAnycomponent] p1: minsilkscreentomaskgap=5 clearancetoexposedcopper=TRUE
SilkToSolderMaskClearance "Silk to Solder Mask Opening" [All] p2: minsilkscreentomaskgap=4 clearancetoexposedcopper=FALSE
SolderMaskExpansion SolderMaskExpansion_NPTH [IsThruPin and (PadIsPlated='false')] p1: expansion=5 istentingtop=FALSE soldermaskfromhole=TRUE
SolderMaskExpansion SolderMaskExpansion_PTH [IsThruPin] p2: expansion=2.5 istentingtop=FALSE
SolderMaskExpansion [All] p3: expansion=0 istentingtop=FALSE
Width [All] p1: maxlimit=100 minlimit=6 preferedwidth=10 checkconnectedcopper=TRUE
14 further rules are at their usual default settings.

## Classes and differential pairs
component class 6_BUF802_PWR_PG2: C104 C109 C110 C111 C112 C113 C115 C116 C117 C118 C123 C124 C125 C126 C127 C128 C129 C130 C131 C132 C133 C134 C135 C136 C137 C138 C139 C140 C141 C145 C146 C147 FB2 FB3 L16 R101 R102 R104 R106 R109 R112 R113 R114 R116 R117 R167 R168 R169 R170 R171 R172 R173 R174 R175 R176 R177 R178 R179 U27 U28 U29 U30 U31
net class Power: +2.5VA +3.8V_IN_TPS7A94 +3P3VD +3V_INP_TPS7A39 +5.5V_IN_TPS7A94 +5VA +8VA +12VA -2.5VA -3.3VA -3V_INN_TPS7A39 -5.5V_IN_TPS7A33 -5VA LM27762_IN
component class Header: J3 J4 J7 J16 J17 J18 J19 J24 J25 J27 J31 J32
component class 5_BUF802_PWR_PG1: C13 C14 C21 C22 C25 C26 C35 C38 C42 C43 C53 C57 C61 C68 C69 C71 C77 C78 C79 C80 C105 C106 C107 C108 C114 C119 C120 C121 C122 C142 C143 C144 C158 C159 C160 C161 C162 C163 C164 C165 C166 C167 C168 C169 C170 C171 FB1 J5 J30 R68 R69 R70 R71 R76 R77 R78 R79 R80 R82 R83 R85 R86 R87 R88 R90 R91 R92 R97 R98 R99 R100 R103 R105 R108 R111 TP1 TP2 TP3 TP4 TP5 TP6 TP7 TP8 TP9 TP11 TP13 TP14 U12 U13 U15 U16 U25 U26
component class 4_BUF802_USBIF: C17 C41 C52 C54 C55 C56 C58 C64 C65 C66 C70 C76 C81 C82 C83 C84 C85 C86 C87 C88 C89 C90 C91 C92 C93 C94 C95 C148 C149 C150 C151 C152 C153 C154 C155 C156 C157 C504 C505 C514 D5 D6 J7 J16 J17 J18 J19 J24 J25 J26 J27 J31 J32 L20 L21 L22 L28 L29 L30 R23 R28 R29 R50 R55 R62 R63 R64 R65 R66 R67 R81 R93 R94 R95 R96 R107 R110 R115 R126 R127 R128 R129 R130 R131 R132 R133 R134 R135 R136 R137 R138 R139 R140 R141 R142 R151 R152 R156 R157 R161 R162 R163 R164 R165 R166 R182 R183 R184 R185 R186 R187 R188 R189 R190 R191 R192 R193 R194 R195 R197 R198 R200 R202 R203 R204 R205 R206 R207 R208 R209 R212 R213 R214 R215 R216 R217 R218 TP10 TP12 U5 U6 U9 U10 U11 U14 U17 U18 U19 U20 U21 U32 U33 Y1
component class 3_BUF802_OFFSET_TRIGGER: C500 C501 C502 C503 C506 C507 C510 C511 C512 C513 C523 C526 C527 C530 C531 C532 C533 C534 C535 C536 C537 C538 C539 C542 C543 C546 C547 C548 C549 C550 C553 C554 C557 C558 C561 C564 C565 C566 C567 C568 C569 L25 L26 L27 L31 L32 L504 L509 L510 L511 L512 L515 L516 R500 R501 R502 R503 R504 R505 R508 R511 R517 R518 R519 R520 R521 R522 R523 R524 R525 R526 R527 R528 R529 R532 R533 R534 R535 R538 R541 R542 R547 R548 R549 R550 R553 R554 R555 R556 U24 U500 U501 U502 U503 U504 U505 U507 U508
component class 2_BUF802_CH2_AFE: C2 C3 C6 C8 C9 C12 C16 C20 C23 C28 C30 C32 C34 C37 C40 C46 C47 C50 C51 C97 C99 C100 C101 C524 C528 C541 C544 C552 C555 C560 C563 H4 H5 H8 H10 H11 H12 J2 J4 J8 J11 J14 J15 J20 J21 J29 L2 L4 L8 L10 L12 L14 L23 L24 L501 L503 L513 MP2 R2 R4 R6 R8 R9 R12 R14 R16 R18 R20 R22 R25 R27 R31 R33 R35 R37 R38 R41 R44 R45 R47 R49 R52 R54 R57 R59 R61 R74 R75 R122 R123 R124 R125 R145 R146 R148 R150 R155 R158 R181 R219 R220 R513 R514 R531 R537 R539 R544 R546 R552 T2 U2 U4 U8 U23
component class 1_BUF802_CH1_AFE: C1 C4 C5 C7 C10 C11 C15 C19 C24 C27 C29 C31 C33 C36 C39 C44 C45 C48 C49 C96 C98 C102 C103 C525 C529 C540 C545 C551 C556 C559 C562 H3 H6 H7 H9 H13 H14 J1 J3 J9 J10 J12 J13 J22 J23 J28 L1 L3 L7 L9 L11 L13 L500 L502 L514 MP1 R1 R3 R5 R7 R10 R11 R13 R15 R17 R19 R21 R24 R26 R30 R32 R34 R36 R39 R40 R42 R43 R46 R48 R51 R53 R56 R58 R60 R72 R73 R118 R119 R120 R121 R143 R144 R147 R149 R154 R159 R180 R515 R516 R530 R536 R540 R543 R545 R551 T1 U1 U3 U7 U22
component class "Mounting Holes": H1 H2 H15 H16
component class Logo: Logo4
component class EVM_Hardware: FID1 FID2 FID3 FID4 FID5 FID6 H1 H2 H15 H16 H500 H501 H502 H503 LBL1 Logo1 Logo2 Logo3 Logo4 ZZ1 ZZ2 ZZ3 ZZ4 ZZ5
component class FiducialMark: FID1 FID2 FID3 FID4 FID5 FID6
component class AssemblyNote: ZZ1 ZZ2 ZZ3 ZZ4 ZZ5
component class Label: LBL1

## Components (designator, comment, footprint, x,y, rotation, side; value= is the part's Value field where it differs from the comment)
C1 "0402BB104KW500" 0402 128.74,2272.46 r90 top locked value=0.1uF
C2 "0402BB104KW500" 0402 128.74,1126.2 r90 top locked value=0.1uF
C3 "CC0805KKX5R8BB106" 0805_HV 192.8,458.73 r0 top locked value=10uF
C4 "CC0805KKX5R8BB106" 0805_HV 192.81,1604.98 r0 top locked value=10uF
C5 "GRM31A5C2J331JW01D" 1206 136,2090 r180 top locked value=330pF
C6 "GRM31A5C2J331JW01D" 1206 140.71,944.54 r180 top locked value=330pF
C7 "CC0805KKX5R8BB106" 0805_HV 196.69,2210.84 r90 top locked value=10uF
C8 "CC0805KKX5R8BB106" 0805_HV 193.69,1077.59 r90 top locked value=10uF
C9 "0402BB104KW500" 0402 209.18,539.55 r0 top locked value=0.1uF
C10 "0402BB104KW500" 0402 209.18,1685.8 r0 top locked value=0.1uF
C11 "GRM1555C1H560JA01D" 0402 237.3,1809.93 r270 top locked value=56pF
C12 "GRM1555C1H560JA01D" 0402 237.3,663.67 r270 top locked value=56pF
C13 "GRM155R71C104KA88D" FP-GRM15-MFG 2465,5585 r180 top value=0.10μF
C14 "C3216X7R1E106M160AE" 1206_190 3538.61,4868.09 r90 top value=10uF
C15 "CGA3E2X7R1H104K080AA" 0603 283.22,2183.77 r90 top locked value=0.1uF
C16 "CGA3E2X7R1H104K080AA" 0603 283.22,1037.52 r90 top locked value=0.1uF
C17 "C0603C104J3RACTU" 0603 1547.86,3573.76 r0 top value=0.1uF
C19 "0402BB104KW500" 0402 343.72,1936.29 r270 top locked value=0.1uF
C20 "0402BB104KW500" 0402 343.72,790.03 r270 top locked value=0.1uF
C21 "C3216X7R1E106M160AE" 1206_190 3538.61,5050.08 r270 top value=10uF
C22 "C0603C475K8PACTU" CAPC1608X87X35NL15T15 3373.37,4855 r0 top value=4.7uF
C23 "CGA3E2X7R1H104K080AA" 0603 526.36,994.64 r0 top locked value=0.1uF
C24 "CGA3E2X7R1H104K080AA" 0603 536.36,2140.9 r0 top locked value=0.1uF
C25 "GRM155R71H103KA88D" 0402 2206.33,4959.84 r90 top value=0.01uF
C26 "C3216X7R1E106M160AE" 1206_190 2301,4847 r0 top value=10uF
C27 "0402BB104KW500" 0402 626.44,1881.7 r270 top locked value=0.1uF
C28 "0402BB104KW500" 0402 626.44,735.44 r270 top locked value=0.1uF
C29 "CC0805KKX5R8BB106" 0805_HV 724.23,2219.82 r180 top locked value=10uF
C30 "CC0805KKX5R8BB106" 0805_HV 724.23,1073.57 r180 top locked value=10uF
C31 "885012205061" 0402 712.5,2067.47 r270 top locked value=1000pF
C32 "885012205061" 0402 712.5,921.22 r270 top locked value=1000pF
C33 "885012205061" 0402 790.35,1737.75 r0 top locked value=1000pF
C34 "885012205061" 0402 790.35,591.49 r0 top locked value=1000pF
C35 "C3216X7R1E106M160AE" 1206_190 2485.4,4847 r180 top value=10uF
C36 "0402BB104KW500" 0402 853.53,2277.4 r90 top locked value=0.1uF
C37 "0402BB104KW500" 0402 853.53,1131.14 r90 top locked value=0.1uF
C38 "GRM155R71H103KA88D" 0402 2239.06,5089.68 r270 top value=0.01uF
C39 "0402BB104KW500" 0402 914.28,1951.14 r180 top locked value=0.1uF
C40 "0402BB104KW500" 0402 914.28,804.88 r180 top locked value=0.1uF
C41 "C0603C104J3RACTU" 0603 961.5,3744.95 r270 top locked value=0.1uF
C42 "C3216X7R1E106M160AE" 1206_190 2488,5185 r180 top value=10uF
C43 "C3216X7R1E106M160AE" 1206_190 2306.54,5184.48 r0 top value=10uF
C44 "LLL185R71E103MA01L" 0306 1038.87,2265.81 r90 top locked value=0.01uF
C45 "LLL185R71E103MA01L" 0306 1038.87,1936.07 r270 top locked value=0.01uF
C46 "LLL185R71E103MA01L" 0306 1038.87,1119.55 r90 top locked value=0.01uF
C47 "LLL185R71E103MA01L" 0306 1040.74,750.12 r270 top locked value=0.01uF
C48 "CGA3E2X7R1H104K080AA" 0603 1164.7,2269.79 r0 top locked value=0.1uF
C49 "CGA3E2X7R1H104K080AA" 0603 1164.29,1927.55 r0 top locked value=0.1uF
C50 "CGA3E2X7R1H104K080AA" 0603 1161.12,1128.48 r0 top locked value=0.1uF
C51 "CGA3E2X7R1H104K080AA" 0603 1162.13,780.31 r0 top locked value=0.1uF
C52 "C0603C104J3RACTU" 0603 1202.08,3739.95 r90 top locked value=0.1uF
C53 "GRM188R71H472KA01D" CAPC1608X90X35ML10T15 2540,5023.48 r180 top value=4.7nF
C54 "C0603C104J3RACTU" 0603 1148.77,3361.48 r0 top value=0.1uF
C55 "C0603C104J3RACTU" 0603 1381.09,4240.45 r270 top locked value=0.1uF
C56 "C0603C104J3RACTU" 0603 619.72,3473.86 r270 top value=0.1uF
C57 "CGA3E2X7R1H104K080AA" 0603 1508,5530.5 r270 top value=0.1uF
C58 "C0603C104J3RACTU" 0603 785.5,3779.11 r180 top value=0.1uF
C61 "C3216X7R1E106M160AE" 1206_190 1597,5495.07 r270 top value=10uF
C64 "C0603C104J3RACTU" 0603 1635.12,4050.71 r180 top locked value=0.1uF
C65 "C0603C104J3RACTU" 0603 1672.52,3981.82 r0 top locked value=0.1uF
C66 "C0603C104J3RACTU" 0603 1672.52,3893.39 r0 top locked value=0.1uF
C68 "C3216X7R1E106M160AE" 1206_190 1734,4926.07 r270 top locked value=10uF
C69 "GRM188R71H472KA01D" CAPC1608X90X35ML10T15 1668.54,4598 r0 top value=4.7nF
C70 "GRM188R61A106ME69D" 0603 1671.77,3663.9 r270 top locked value=10uF
C71 "C3216X7R1E106M160AE" 1206_190 1733.14,4740.37 r90 top locked value=10uF
C76 "C0603C104J3RACTU" 0603 1734.18,3663.9 r90 top locked value=0.1uF
C77 "GRM188R71H472KA01D" CAPC1608X90X35ML10T15 1384.14,4599.71 r180 top value=4.7nF
C78 "C3216X7R1E106M160AE" 1206_190 1373,4923 r270 top locked value=10uF
C79 "C3216X7R1E106M160AE" 1206_190 1373.14,4740.37 r90 top locked value=10uF
C80 "GRM188R71H472KA01D" CAPC1608X90X35ML10T15 1525.46,4958 r0 top value=4.7nF
C81 "C0603C104J3RACTU" 0603 1741.14,3521.81 r90 top locked value=0.1uF
C82 "C0603C104J3RACTU" 0603 1886.08,4321.06 r270 top locked value=0.1uF
C83 "C0603C104J3RACTU" 0603 2079.77,4319.88 r270 top locked value=0.1uF
C84 "C0603C104J3RACTU" 0603 2184.66,4447.41 r180 top locked value=0.1uF
C85 "C0603C104J3RACTU" 0603 2368.57,3108.53 r270 top locked value=0.1uF
C86 "C0603C104J3RACTU" 0603 2483.93,3737.23 r180 top locked value=0.1uF
C87 "C0603C104J3RACTU" 0603 2483.93,3986.84 r180 top locked value=0.1uF
C88 "C0603C104J3RACTU" 0603 2483.93,4111.64 r180 top locked value=0.1uF
C89 "C0603C104J3RACTU" 0603 2483.93,4236.45 r0 top locked value=0.1uF
C90 "GRM1885C2A160JA01D" 0603 2491.76,3514.63 r270 top locked value=16pF
C91 "GRM1885C2A160JA01D" 0603 2587.91,3291.29 r180 top locked value=16pF
C92 "C1608X7R1C105K080AC" 0603 2769.37,3757.97 r180 top locked value=1uF
C93 "C1608X7R1C105K080AC" 0603 2769.37,3472.37 r180 top locked value=1uF
C94 "GRM32ER61A107ME20L" 1210_270 2920.95,3220.71 r0 top locked value=100uF
C95 "C0603C104J3RACTU" 0603 2895.36,3317.56 r180 top locked value=0.1uF
C96 "CGA3E2X7R1H104K080AA" 0603 2999.17,2717.1 r0 top locked value=0.1uF
C97 "CGA3E2X7R1H104K080AA" 0603 2999.17,1570.84 r0 top locked value=0.1uF
C98 "CGA3E2X7R1H104K080AA" 0603 3141.84,2717.1 r0 top locked value=0.1uF
C99 "CGA3E2X7R1H104K080AA" 0603 3141.84,1570.84 r0 top locked value=0.1uF
C100 "C1005X7R1E104M050BB" 0402 3259.52,1470.68 r0 top locked value=0.1uF
C101 "C1005X7R1E104M050BB" 0402 3259.52,1423.44 r0 top locked value=0.1uF
C102 "C1005X7R1E104M050BB" 0402 3259.53,2616.94 r0 top locked value=0.1uF
C103 "C1005X7R1E104M050BB" 0402 3259.53,2569.69 r0 top locked value=0.1uF
C104 "GRM155R71C104KA88D" FP-GRM15-MFG 355.71,5478 r180 top value=0.10μF
C105 "C3216X7R1E106M160AE" 1206_190 2461.83,5661.92 r0 top value=10uF
C106 "C2012X5R1C226K125AC" 0805_HV 2665.55,5438.9 r270 top locked value=22uF
C107 "C2012X5R1C226K125AC" 0805_HV 2767.59,5438.95 r270 top locked value=22uF
C108 "C2012X5R1C226K125AC" 0805_HV 2869.65,5437.76 r270 top locked value=22uF
C109 "C3216X7R1E106M160AE" 1206_190 406.89,5562 r0 top value=10uF
C110 "GRM21BD71A226ME44L" 0805_HV 555.41,5321.85 r270 top locked value=22uF
C111 "GRM21BD71A226ME44L" 0805_HV 654.83,5321.57 r270 top locked value=22uF
C112 "GRM21BD71A226ME44L" 0805_HV 754.37,5322.42 r270 top locked value=22uF
C113 "GRM155R71C104KA88D" FP-GRM15-MFG 119.75,4952 r180 top value=0.10μF
C114 "C0603C475K8PACTU" CAPC1608X87X35NL15T15 2895,5104.57 r270 top value=4.7uF
C115 "C3216X7R1E106M160AE" 1206_190 117.62,5030.35 r0 top value=10uF
C116 "C3216X7R1E106M160AE" 1206_190 117.21,5122.02 r0 top value=10uF
C117 "GRM31CR71A226KE15L" FP-GRM31C-0_2-e0_3_0_8-MFG 233.46,4840.35 r90 top
C118 "GRM31CR71A226KE15L" FP-GRM31C-0_2-e0_3_0_8-MFG 321.7,4840.35 r90 top
C119 "C0603C475K8PACTU" CAPC1608X87X35NL15T15 2895,4994.97 r90 top value=4.7uF
C120 "C1608X5R1C474K080AA" FP-C1608-080-0_1-MFG 2674.73,5071.53 r0 top
C121 "C1608X7R1A225K080AC" 0603 2679.5,5001.85 r180 top value=2.2uF
C122 "C1608X7R1A225K080AC" 0603 2832,5167.5 r270 top value=2.2uF
C123 "C3216X7R1E106M160AE" 1206_190 327.5,4258.53 r0 top value=10uF
C124 "C3216X7R1E106M160AE" 1206_190 153.81,4383 r0 top value=10uF
C125 "GRM31CR71A226KE15L" FP-GRM31C-0_2-e0_3_0_8-MFG 410.39,4840.35 r90 top
C126 "GRM31CR71A226KE15L" FP-GRM31C-0_2-e0_3_0_8-MFG 499.4,4840.35 r90 top
C127 "GRM31CR71A226KE15L" FP-GRM31C-0_2-e0_3_0_8-MFG 587.85,4840.35 r90 top
C128 "GRM31CR71A226KE15L" FP-GRM31C-0_2-e0_3_0_8-MFG 677.7,4840.35 r90 top
C129 "GRM155R71H103KA88D" 0402 1073.69,4738.72 r0 top value=0.01uF
C130 "C3216X7R1E106M160AE" 1206_190 932,4875.37 r270 top value=10uF
C131 "C1608X5R1A106K080AC" FP-C1608-080-0_1-MFG 936.44,4664 r0 top
C132 "C0603C475K8PACTU" CAPC1608X87X35NL15T15 253,4157.74 r90 top value=4.7uF
C133 "C0603C475K8PACTU" CAPC1608X87X35NL15T15 319.18,4157.74 r90 top value=4.7uF
C134 "C3216X7R1E106M160AE" 1206_190 287,3824.07 r270 top value=10uF
C135 "C1608X5R1A106K080AC" FP-C1608-080-0_1-MFG 936.44,4741 r0 top
C136 "C3216X7R1E106M160AE" 1206_190 124.97,4004.34 r0 top value=10uF
C137 "GRM31CR71A226KE15L" FP-GRM31C-0_2-e0_3_0_8-MFG 681.4,4610.34 r270 top locked
C138 "GRM31CR71A226KE15L" FP-GRM31C-0_2-e0_3_0_8-MFG 592.65,4610.34 r270 top locked
C139 "GRM31CR71A226KE15L" FP-GRM31C-0_2-e0_3_0_8-MFG 503.9,4609.81 r270 top locked
C140 "GRM31CR71A226KE15L" FP-GRM31C-0_2-e0_3_0_8-MFG 416.11,4609.97 r270 top locked
C141 "C1608X7R1C105K080AC" 0603 1103.22,5045 r0 top value=1uF
C142 "C2012X5R1C226K125AC" 0805_HV 3041,5443.98 r90 top locked value=22uF
C143 "C2012X5R1C226K125AC" 0805_HV 3131,5443.98 r90 top locked value=22uF
C144 "GRM188R71C224KA01D" 0603 2286.14,5489 r180 top value=0.22uF
C145 "GRM21BD71A226ME44L" 0805_HV 749.55,5158.31 r270 top value=22uF
C146 "GRM21BD71A226ME44L" 0805_HV 849.55,5158.31 r270 top value=22uF
C147 "GRM188R71C224KA01D" 0603 183,5364 r180 top value=0.22uF
C500 "0402BB104KW500" 0402 2836.56,2586.33 r90 bottom locked value=0.1uF
C501 "0402BB104KW500" 0402 2836.56,1440.08 r90 bottom locked value=0.1uF
C502 "0402BB104KW500" 0402 2663.52,2474.41 r180 bottom locked value=0.1uF
C503 "0402BB104KW500" 0402 2663.51,1328.15 r180 bottom locked value=0.1uF
C504 "GRM188R61A106ME69D" 0603 2483.93,3986.84 r0 bottom locked value=10uF
C505 "GRM188R61A106ME69D" 0603 2483.93,3737.23 r0 bottom locked value=10uF
C506 "0402BB104KW500" 0402 2392.83,2625.7 r180 bottom locked value=0.1uF
C507 "0402BB104KW500" 0402 2392.82,1479.45 r180 bottom locked value=0.1uF
C510 "C3216X7R1E106M160AE" 1206_190 1812.89,3069.82 r180 bottom value=10uF
C511 "C3216X7R1E106M160AE" 1206_190 1814.2,2767.44 r180 bottom value=10uF
C512 "CGA3E2X7R1H104K080AA" 0603 1796.74,2995.84 r0 bottom locked value=0.1uF
C513 "CGA3E2X7R1H104K080AA" 0603 1801.27,2842.57 r0 bottom value=0.1uF
C514 "GRM32ER61A107ME20L" 1210_270 1686.77,3638.31 r270 bottom locked value=100uF
C523 "0402BB104KW500" 0402 1047.55,135.48 r90 bottom locked value=0.1uF
C524 "CC0805KKX5R8BB106" 0805_HV 906.41,729.88 r180 bottom locked value=10uF
C525 "CC0805KKX5R8BB106" 0805_HV 906.41,1876.14 r180 bottom locked value=10uF
C526 "0402BB104KW500" 0402 915.79,1473.79 r90 bottom locked value=0.1uF
C527 "CGA3E2X7R1H104K080AA" 0603 867.3,143.36 r270 bottom locked value=0.1uF
C528 "0402BB104KW500" 0402 853.53,1131.14 r90 bottom locked value=0.1uF
C529 "0402BB104KW500" 0402 853.53,2277.4 r90 bottom locked value=0.1uF
C530 "CGA3E2X7R1H104K080AA" 0603 819.29,3471.65 r270 bottom locked value=0.1uF
C531 "0402BB104KW500" 0402 784.45,35.15 r0 bottom locked value=0.1uF
C532 "0402BB104KW500" 0402 740.52,3146.18 r180 bottom locked value=0.1uF
C533 "CGA3E2X7R1H104K080AA" 0603 735.47,1481.66 r270 bottom locked value=0.1uF
C534 "C3216X7R1E106M160AE" 1206_190 665.18,2918.69 r180 bottom locked value=10uF
C535 "C3216X7R1E106M160AE" 1206_190 664.98,2581.09 r180 bottom locked value=10uF
C536 "CC0805KKX5R8BB106" 0805_HV 681.69,3480.15 r90 bottom locked value=10uF
C537 "0402BB104KW500" 0402 674,1386 r0 bottom value=0.1uF
C538 "CGA3E2X7R1H104K080AA" 0603 629.74,2843.49 r0 bottom locked value=0.1uF
C539 "CGA3E2X7R1H104K080AA" 0603 629.54,2656.29 r0 bottom locked value=0.1uF
C540 "CC0805KKX5R8BB106" 0805_HV 626.44,1898.08 r270 bottom locked value=10uF
C541 "CC0805KKX5R8BB106" 0805_HV 626.44,751.82 r270 bottom locked value=10uF
C542 "0402BB104KW500" 0402 609.25,253.22 r0 bottom locked value=0.1uF
C543 "0402BB104KW500" 0402 613.38,3463.78 r90 bottom locked value=0.1uF
C544 "CC0805KKX5R8BB106" 0805_HV 552,905.47 r0 bottom locked value=10uF
C545 "CC0805KKX5R8BB106" 0805_HV 552,2051.73 r0 bottom locked value=10uF
C546 "0402BB104KW500" 0402 586.51,3230.94 r270 bottom locked value=0.1uF
C547 "GRM155R71H103KA88D" 0402 564.76,3463.78 r90 bottom locked value=0.01uF
C548 "GMK316AB7106KL" 1206 528.03,3077.4 r270 bottom locked value=10uF
C549 "CGA3E2X7R1H104K080AA" 0603 496.54,3354.36 r0 bottom locked value=0.1uF
C550 "0402BB104KW500" 0402 497.43,1591.52 r0 bottom locked value=0.1uF
C551 "0402BB104KW500" 0402 507.45,1953.13 r90 bottom locked value=0.1uF
C552 "0402BB104KW500" 0402 507.45,806.88 r90 bottom locked value=0.1uF
C553 "CGA3E2X7R1H104K080AA" 0603 472.06,132.57 r270 bottom locked value=0.1uF
C554 "C0603X104K4RACTU" 0603 445.55,3102.99 r270 bottom locked value=0.1uF
C555 "0402BB104KW500" 0402 402,870 r180 bottom locked value=0.1uF
C556 "0402BB104KW500" 0402 412.43,2022.95 r180 bottom locked value=0.1uF
C557 "0402BB104KW500" 0402 403.4,-17.12 r90 bottom locked value=0.1uF
C558 "CGA3E2X7R1H104K080AA" 0603 360.23,1470.88 r270 bottom locked value=0.1uF
C559 "0402BB104KW500" 0402 343.72,1936.29 r270 bottom locked value=0.1uF
C560 "0402BB104KW500" 0402 343.72,790.03 r270 bottom locked value=0.1uF
C561 "GRM155R71H103KA88D" 0402 317.11,3456.22 r270 bottom locked value=0.01uF
C562 "C0603C209C5GACTU" 0603 286.05,1936.87 r270 bottom locked value=2pF
C563 "C0603C209C5GACTU" 0603 286.05,790.62 r270 bottom locked value=2pF
C564 "0402BB104KW500" 0402 291.91,1327.84 r90 bottom locked value=0.1uF
C565 "0402BB104KW500" 0402 268.49,3456.22 r270 bottom locked value=0.1uF
C566 "CC0805KKX5R8BB106" 0805_HV 200.18,3439.84 r270 bottom locked value=10uF
C567 "0402BB104KW500" 0402 69.46,3440.47 r90 bottom locked value=0.1uF
C568 "CGA3E2X7R1H104K080AA" 0603 30.75,3132.99 r270 bottom locked value=0.1uF
C569 "GMK316AB7106KL" 1206 -54.37,3107.4 r270 bottom locked value=10uF
D5 "LTST-C191TGKT" LTST-C191_Green 1674.49,3828.94 r180 top locked value=Green
D6 "LTST-C191TGKT" LTST-C191_Green 2113.77,3521.74 r90 top locked value=Green
FB1 "BLE18PS080SN1D" FP-BLE18PS080SN1D_0603-IPC_B 2961,5438.43 r270 top locked
FB2 "BLE18PS080SN1D" FP-BLE18PS080SN1D_0603-IPC_B 842.55,5328.5 r270 top locked
FB3 "BLE18PS080SN1D" FP-BLE18-0_15-t0_6-IPC_B 781,4871.81 r270 top
FID1 "Fiducial" Fiducial10-20 0,5550 r0 top locked
FID2 "Fiducial" Fiducial10-20 0,250 r90 top locked
FID3 "Fiducial" Fiducial10-20 3250,0 r0 top locked
FID4 "Fiducial" Fiducial10-20 0,5550 r270 bottom
FID5 "Fiducial" Fiducial10-20 3250,0 r180 bottom locked
FID6 "Fiducial" Fiducial10-20 0,250 r270 bottom locked
H1 "NY PMS 440 0025 PH" "NY PMS 440 0025 PH" 0,5800 r0 top
H2 "NY PMS 440 0025 PH" "NY PMS 440 0025 PH" 0,0 r0 top locked
H3 "S1721-46R" Harwin_S1721-46R -53.51,2381.03 r90 top locked
H4 "S1721-46R" Harwin_S1721-46R -53.51,1235.11 r90 top locked
H5 "S1721-46R" Harwin_S1721-46R -53.51,551.47 r90 top locked
H6 "S1721-46R" Harwin_S1721-46R -53.51,1697.72 r270 top locked
H7 "S1721-46R" Harwin_S1721-46R 900.38,2529.38 r180 top locked
H8 "S1721-46R" Harwin_S1721-46R 900.38,403.45 r180 top locked
H9 "S1721-46R" Harwin_S1721-46R 900.38,1549.38 r180 top locked
H10 "S1721-46R" Harwin_S1721-46R 900.38,1383.45 r180 top locked
H11 "S1721-46R" Harwin_S1721-46R 1426.49,1235.11 r270 top locked
H12 "S1721-46R" Harwin_S1721-46R 1426.49,551.8 r270 top locked
H13 "S1721-46R" Harwin_S1721-46R 1426.49,2381.03 r270 top locked
H14 "S1721-46R" Harwin_S1721-46R 1426.49,1697.72 r270 top locked
H15 "NY PMS 440 0025 PH" "NY PMS 440 0025 PH" 3500,5800 r0 top
H16 "NY PMS 440 0025 PH" "NY PMS 440 0025 PH" 3500,0 r0 top locked
H500 "1902E" Keystone_1902E 3500,5800 r180 bottom
H501 "1902E" Keystone_1902E 3500,0 r180 bottom
H502 "1902E" Keystone_1902E 0,5800 r180 bottom
H503 "1902E" Keystone_1902E 0,0 r180 bottom
J1 "142-0701-851" Emerson_142-0701-851 -300,2090.92 r90 top locked
J2 "142-0701-851" Emerson_142-0701-851 -300,945 r90 top locked
J3 "22284030" Molex_0022284030 -134.53,1544.06 r90 top locked
J4 "22284030" Molex_0022284030 -134.53,397.81 r90 top locked
J5 "1581-2" Pomona_1581-2 1900.44,5751.15 r180 top
J7 "TSW-110-07-G-D" TSW-110-07-G-D 2537.48,4649 r180 top locked
J8 "SASF546-P26-X1" CONN_LTI_SASF546-P26-X1 1650,625 r0 top locked
J9 "SASF546-P26-X1" CONN_LTI_SASF546-P26-X1 1650,1770 r0 top locked
J10 "SASF546-P26-X1" CONN_LTI_SASF546-P26-X1 1650,2430 r180 top locked
J11 "SASF546-P26-X1" CONN_LTI_SASF546-P26-X1 1650,1285 r0 top
J12 "SASF546-P26-X1" CONN_LTI_SASF546-P26-X1 2050,2305 r90 top locked
J13 "SASF546-P26-X1" CONN_LTI_SASF546-P26-X1 2050,1895 r270 top locked
J14 "SASF546-P26-X1" CONN_LTI_SASF546-P26-X1 2050,1160 r0 top
J15 "SASF546-P26-X1" CONN_LTI_SASF546-P26-X1 2050,750 r270 top locked
J16 "61301021121" WURTH_61301021121 2918.16,4198.56 r0 top locked
J17 "22284030" Molex_0022284030 2911.33,3642.21 r270 top locked
J18 "22284030" Molex_0022284030 3041.57,3642.21 r270 top locked
J19 "22284030" Molex_0022284030 3171.8,3642.21 r270 top locked
J20 "SASF546-P26-X1" CONN_LTI_SASF546-P26-X1 3283.15,1772.06 r180 top locked
J21 "SASF546-P26-X1" CONN_LTI_SASF546-P26-X1 3283.15,1122.06 r180 top locked
J22 "SASF546-P26-X1" CONN_LTI_SASF546-P26-X1 3283.15,2918.32 r180 top locked
J23 "SASF546-P26-X1" CONN_LTI_SASF546-P26-X1 3283.15,2268.31 r180 top locked
J24 "22284030" Molex_0022284030 3302.04,3642.21 r270 top locked
J25 "22284030" Molex_0022284030 3432.28,3642.21 r270 top locked
J26 "678038020" FP-678038020_CONN_USB-MFG 3701.57,4243.19 r180 top locked
J27 "22284030" Molex_0022284030 3562.51,3642.21 r270 top locked
J28 "SASF546-P26-X1" CONN_LTI_SASF546-P26-X1 2500,2100 r0 top locked
J29 "SASF546-P26-X1" CONN_LTI_SASF546-P26-X1 2500,955 r0 top locked
J30 "1581-0" Pomona_1581-0 1198.24,5737.57 r0 top
J31 "22284030" Molex_0022284030 1951.03,2983.36 r270 top
J32 "22284030" Molex_0022284030 2501.29,2883.22 r0 top
L1 "LQG15WZ6N8J02D" LQG15WZ_02 57.35,2002.29 r0 top locked value=6.8nH
L2 "LQG15WZ6N8J02D" LQG15WZ_02 59,845 r0 top locked value=6.8nH
L3 "BLM18SG121TN1D" 0603 349.3,1604.98 r0 top locked value="120 ohm"
L4 "BLM18SG121TN1D" 0603 349.3,458.73 r0 top locked value="120 ohm"
L7 "BLM18SG121TN1D" 0603 507.45,1945.26 r270 top locked value="120 ohm"
L8 "BLM18SG121TN1D" 0603 507.45,799 r270 top locked value="120 ohm"
L9 "BLM18SG121TN1D" 0603 681.95,1889.57 r90 top locked value="120 ohm"
L10 "BLM18SG121TN1D" 0603 681.95,743.32 r90 top locked value="120 ohm"
L11 "BLM18SG121TN1D" 0603 732.73,2294.82 r0 top locked value="120 ohm"
L12 "BLM18SG121TN1D" 0603 732.73,1148.57 r180 top locked value="120 ohm"
L13 "BLM18SG121TN1D" 0603 906.41,1876.14 r0 top locked value="120 ohm"
L14 "BLM18SG121TN1D" 0603 906.41,729.88 r0 top locked value="120 ohm"
L16 "XGL4020-222MEC" FP-XGL4020-MFG 181.02,4659.45 r0 top locked
L20 "BLM18SG260TN1D" 0603 2483.93,3674.83 r0 top locked value="26 ohm"
L21 "BLM18SG260TN1D" 0603 2483.93,4049.24 r180 top locked value="26 ohm"
L22 "BLM18SG260TN1D" 0603 2863.86,3415.87 r270 top locked value="26 ohm"
L500 "BLM18SG121TN1D" 0603 3141.84,2717.1 r0 bottom locked value="120 ohm"
L501 "BLM18SG121TN1D" 0603 3141.84,1570.84 r0 bottom locked value="120 ohm"
L502 "BLM18SG121TN1D" 0603 2999.17,2717.1 r0 bottom locked value="120 ohm"
L503 "BLM18SG121TN1D" 0603 2999.17,1570.84 r0 bottom locked value="120 ohm"
L504 "BLM18SG121TN1D" 0603 2480.77,2714.08 r270 bottom locked value="120 ohm"
L509 "BLM18SG121TN1D" 0603 756.89,3471.65 r270 bottom locked value="120 ohm"
L510 "BLM18SG121TN1D" 0603 505.14,1647.03 r180 bottom locked value="120 ohm"
L511 "BLM18SG121TN1D" 0603 493.62,2918.69 r180 bottom locked value="120 ohm"
L512 "BLM18SG121TN1D" 0603 423.9,2576.82 r0 bottom locked value="120 ohm"
L513 "BLM18SG121TN1D" 0603 196.69,1056.09 r90 bottom locked value="120 ohm"
L514 "BLM18SG121TN1D" 0603 196.69,2202.34 r90 bottom locked value="120 ohm"
L515 "BLM18SG121TN1D" 0603 124.97,3448.34 r90 bottom locked value="120 ohm"
L516 "BLM18SG121TN1D" 0603 -54.37,3273.62 r90 bottom locked value="120 ohm"
LBL1 "THT-14-423-10" Label_650x200 3594.34,559.02 r90 top
Logo1 "CE Mark" CE_Mark_5mm 1424.68,-131.22 r0 top locked
Logo2 "FCC disclaimer" FCC_disclaimer 1360.65,-94.33 r0 top locked
Logo3 "WEEE logo" WEEE_Minimum 1787.58,-48.41 r0 top locked
Logo4 "Texas Instruments" TI_Stacked_Overlay_Small 2561.31,-23.89 r0 top
MP1 "1.0 x 1.5 x 0.25" "FP-1.0 x 1.5 x 0.25_RF_SHIELD-MFG" 686.49,2039.38 r90 top locked
MP2 "1.0 x 1.5 x 0.25" "FP-1.0 x 1.5 x 0.25_RF_SHIELD-MFG" 686.49,893.45 r90 top locked
R1 "RC0603FR-07330RL" 0603 12.35,1844.72 r90 top locked value=330
R2 "RC0603FR-07330RL" 0603 12.35,698.47 r90 top locked value=330
R3 "FC0603E50R0BTBST1" 0603 45,1943 r180 top locked value=50
R4 "FC0603E50R0BTBST1" 0603 45,795 r180 top locked value=50
R5 "CRCW040230R0JNED" 0402 -13,2091 r0 top locked value=30
R6 "CRCW040230R0JNED" 0402 -9,945 r0 top locked value=30
R7 "CRCW040213K0FKED" 0402L 67.77,1856.53 r90 top locked value=13.0k
R8 "CRCW040213K0FKED" 0402L 67.77,710.28 r90 top locked value=13.0k
R9 "CRCW06030000Z0EA" 0603 191,750.77 r0 top locked value=0
R10 "CRCW06030000Z0EA" 0603 191,1897.02 r0 top locked value=0
R11 "CRCW040220K0FKED" 0402 159.5,1809.93 r270 top locked value=20.0k
R12 "CRCW040220K0FKED" 0402 159.5,663.67 r270 top locked value=20.0k
R13 "CRCW0402787KFKED" 0402L 218.02,1735.81 r180 top locked value=787k
R14 "CRCW0402787KFKED" 0402L 218.02,589.55 r180 top locked value=787k
R15 "CRCW040210M0FKED" 0402 261.14,2067.48 r270 top locked value=10.0Meg
R16 "CRCW040210M0FKED" 0402 261.14,921.22 r270 top locked value=10.0Meg
R17 "ERJ-2RKF2001X" 0402 296.02,1936.34 r90 top locked value=2.00k
R18 "ERJ-2RKF2001X" 0402 296.02,790.09 r90 top locked value=2.00k
R19 "ERJ-2GE0R00X" FP-ERJ-2GE0R00X_0402-MFG 401.22,1941.32 r270 top locked value=0
R20 "ERJ-2GE0R00X" FP-ERJ-2GE0R00X_0402-MFG 401.22,795.06 r270 top locked value=0
R21 "CRCW040217K8FKED" 0402 443.05,1937.38 r90 top locked value=17.8k
R22 "CRCW040217K8FKED" 0402 443.05,791.13 r90 top locked value=17.8k
R23 "CRCW060310K0JNEA" 0603 455.93,3626.44 r270 top locked value=10k
R24 "RC0603JR-071KL" 0603 497.86,2243.62 r90 top locked value=1.0k
R25 "RC0603JR-071KL" 0603 497.86,1097.36 r90 top locked value=1.0k
R26 "CRCW040278K7FKED" 0402 547.12,2041.85 r180 top locked value=78.7k
R27 "CRCW040278K7FKED" 0402 547.12,895.59 r180 top locked value=78.7k
R28 "CRCW060310K0JNEA" 0603 1952.27,3210.77 r90 top value=10k
R29 "CRCW060310K0JNEA" 0603 2266.87,2884.55 r180 top value=10k
R30 "CRCW04021K30FKED" 0402 560.74,1940.23 r90 top locked value=1.30k
R31 "CRCW04021K30FKED" 0402 560.74,793.97 r90 top locked value=1.30k
R32 "CRCW0402499KFKED" 0402 637.1,1682.66 r0 top locked value=499k
R33 "CRCW0402499KFKED" 0402 637.1,536.41 r0 top locked value=499k
R34 "CRCW0402499KFKED" 0402 613.48,1761.37 r270 top locked value=499k
R35 "CRCW0402499KFKED" 0402 613.48,615.12 r270 top locked value=499k
R36 "CRCW0402100RFKED" 0402 653.88,2067.47 r270 top locked value=100
R37 "CRCW0402100RFKED" 0402 653.88,921.22 r270 top locked value=100
R38 "CRCW0402499KFKED" 0402 689.1,591.49 r0 top locked value=499k
R39 "CRCW0402499KFKED" 0402 689.1,1737.75 r0 top locked value=499k
R40 "CRCW040215R0FKED" 0402 744.49,2146.9 r0 top locked value=15.0
R41 "CRCW040215R0FKED" 0402 744.49,1000.65 r0 top locked value=15.0
R42 "CRCW0402200RFKED" 0402 790.35,1880.86 r180 top locked value=200
R43 "CRCW0402200RFKED" 0402 790.35,1809.31 r0 top locked value=200
R44 "CRCW0402200RFKED" 0402 790.35,734.61 r180 top locked value=200
R45 "CRCW0402200RFKED" 0402 790.35,663.05 r0 top locked value=200
R46 "CRCW040215R0FKED" 0402 771.12,2067.47 r90 top locked value=15.0
R47 "CRCW040215R0FKED" 0402 771.12,921.22 r90 top locked value=15.0
R48 "CRCW060375R0FKEA" 0603 827.59,2398.32 r270 top locked value=75.0
R49 "CRCW060375R0FKEA" 0603 827.59,1252.06 r270 top locked value=75.0
R50 "CRCW060310K0JNEA" 0603 885.22,3614.63 r90 top locked value=10k
R51 "CRCW0603237RFKEA" 0603 889.99,2398.32 r90 top locked value=237
R52 "CRCW0603237RFKEA" 0603 889.99,1252.06 r90 top locked value=237
R53 "CRCW04020000Z0EDHP" FP-CRCW04020000Z0EDHP_0402-MFG 903.22,2277.4 r90 top locked value=0
R54 "CRCW04020000Z0EDHP" FP-CRCW04020000Z0EDHP_0402-MFG 903.22,1131.14 r90 top locked value=0
R55 "CRCW060310K0JNEA" 0603 1618.56,3348.03 r270 top value=10k
R56 "CRCW0603237RFKEA" 0603 952.9,2398.32 r90 top locked value=237
R57 "CRCW0603237RFKEA" 0603 952.91,1252.06 r90 top locked value=237
R58 "CRCW04020000Z0EDHP" FP-CRCW04020000Z0EDHP_0402-MFG 952.9,2277.4 r90 top locked value=0
R59 "CRCW04020000Z0EDHP" FP-CRCW04020000Z0EDHP_0402-MFG 952.91,1131.14 r90 top locked value=0
R60 "CRCW060375R0FKEA" 0603 1015.31,2398.32 r270 top locked value=75.0
R61 "CRCW060375R0FKEA" 0603 1015.31,1252.06 r270 top locked value=75.0
R62 "CRCW0603200KFKEA" 0603 1086.63,3771.44 r180 top locked value=200k
R63 "CRCW060310K0JNEA" 0603 1949.77,2743.05 r90 top value=10k
R64 "CRCW060310K0JNEA" 0603 2741.35,2885.33 r180 top value=10k
R65 "CRCW060310K0JNEA" 0603 1484.16,3345.2 r270 top value=10k
R66 "CRCW060310K0JNEA" 0603 1410.08,3346.03 r270 top value=10k
R67 "CRCW060310K0JNEA" 0603 1563.09,3346.41 r270 top value=10k
R68 "CRCW060310K0JNEA" 0603 3453,5115.48 r270 top value=10k
R69 "CRCW060310K0JNEA" 0603 3386,5115.48 r270 top value=10k
R70 "CRCW060310K0JNEA" 0603 3619.26,5051.59 r90 top value=10k
R71 "CRCW060310K0JNEA" 0603 3274.5,4940 r0 top value=10k
R72 "RC0603FR-073K74L" 0603 1164.7,2332.19 r0 top locked value=3.74k
R73 "RC0603FR-073K74L" 0603 1164.29,1865.14 r0 top locked value=3.74k
R74 "RC0603FR-073K74L" 0603 1161.12,1190.88 r0 top locked value=3.74k
R75 "RC0603FR-073K74L" 0603 1162.13,717.91 r0 top locked value=3.74k
R76 "CRCW060310K0JNEA" 0603 3274.5,5016.08 r0 top value=10k
R77 "CRCW060322K1FKEA" RESC1609X50X30LL10T20 3377.31,4795 r0 top value=22.1k
R78 "CRCW04020000Z0EDHP" FP-CRCW04020000Z0EDHP_0402-MFG 3231.61,5387.73 r0 top locked value="0 (DNP)"
R79 "CRCW04020000Z0EDHP" FP-CRCW04020000Z0EDHP_0402-MFG 3232.62,5332.98 r0 top locked value=0
R80 "CRCW060315K4FKEA" RESC1609X50X30LL10T20 2295,5345 r180 top value=15.4k
R81 "CRCW06030000Z0EA" 0603 2051.26,3522.55 r270 top value=0
R82 "ERJ-3EKF4871V" RESC1608X55X30ML15T15 2289.09,5410 r0 top value=4.87k
R83 "CRCW060311K0FKEA" RESC1609X50X30ML10T20 2279.45,4956.89 r270 top value=11k
R85 "CRCW060310K0JNEA" 0603 2139,4951.97 r90 top value=10k
R86 "CRCW04020000Z0EDHP" FP-CRCW04020000Z0EDHP_0402-MFG 2687.38,4937 r180 top value=0
R87 "CRCW060321K0FKEA" RESC1609X50X30LL10T20 2292.86,5090.66 r90 top value=21k
R88 "CRCW04020000Z0EDHP" FP-CRCW04020000Z0EDHP_0402-MFG 2687.38,4881.32 r180 top value="0 (DNP)"
R90 "ERJ3EKF8202V" RESC1608X55X30LL15T15 2803.04,4935.53 r180 top value=82k
R91 "CRCW060375K0FKEA" RESC1609X50X30NL10T20 2919.61,4906 r180 top value=75k
R92 "CRCW04020000Z0EDHP" FP-CRCW04020000Z0EDHP_0402-MFG 2739.38,5238 r180 top value="0 (DNP)"
R93 "CRCW060310K0JNEA" 0603 1284.19,3515.82 r270 top value=10k
R94 "CRCW060310K0JNEA" 0603 1310.76,3889.3 r90 top locked value=10k
R95 "CRCW060310K0JNEA" 0603 1346.59,3515.82 r270 top value=10k
R96 "CRCW060310K0JNEA" 0603 1374.31,3889.75 r90 top locked value=10k
R97 "CRCW060310K0JNEA" 0603 2139.5,5049 r180 top value=10k
R98 "CRCW060351K1FKEA" RESC1609X50X30ML10T20 2666.91,5152.29 r180 top value=51.1k
R99 "ERJ-3EKF5362V" RESC1608X55X30NL15T15 2765.19,5157.43 r270 top value=53.6k
R100 "CRCW04020000Z0EDHP" FP-CRCW04020000Z0EDHP_0402-MFG 2740.01,5292.03 r180 top value=0
R101 "KRL2012E-M-R006-F-T5" FP-KRL2012E-M-R006-F-T5_0805-MFG 297.01,4372.03 r0 top value=6m
R102 "CRCW060310K0JNEA" 0603 -15.75,4286 r0 top value=10k
R103 "ERJ-3EKF5762V" RESC1608X55X30ML15T15 1616.68,4717.37 r0 top locked value=57.6k
R104 "CRCW060310K0JNEA" 0603 -15.75,4219 r0 top value=10k
R105 "CRCW060310K0JNEA" 0603 1671.5,4517 r180 top value=10k
R106 "CRCW060310K0JNEA" 0603 -23.5,4383 r0 top value=10k
R107 "CRCW06030000Z0EA" 0603 1531.18,4171.65 r270 top locked value=0
R108 "ERJ-3EKF2802V" RESC1608X55X30LL15T15 1503.53,4720.37 r180 top value=28k
R109 "CRCW060310K0JNEA" 0603 -15.75,4137.42 r0 top value=10k
R110 "CRCW0603270RJNEA" 0603 1566.06,3860.44 r270 top locked value=270
R111 "CRCW060310K0JNEA" 0603 1526,4616 r0 top locked value=10k
R112 "CRCW060310K0JNEA" 0603 137.91,4137.42 r180 top value=10k
R113 "JR0805X35E" FP-JR0805X35E_0805-MFG 581,5155 r270 top value="0 (DNP)"
R114 "JR0805X35E" FP-JR0805X35E_0805-MFG 658,5155 r270 top value=0
R115 "CRCW06030000Z0EA" 0603 1672.52,3765.28 r180 top locked value=0
R116 "ERJ-3EKF3322V" RESC1608X55X30NL15T15 386,4157.74 r90 top value=33.2k
R117 "ERJ-3EKF3322V" RESC1608X55X30NL15T15 446,4157.74 r90 top value=33.2k
R118 "CRCW04020000Z0EDHP" FP-CRCW04020000Z0EDHP_0402-MFG 1085,2015 r0 top value="0 (DNP)"
R119 "CRCW04020000Z0EDHP" FP-CRCW04020000Z0EDHP_0402-MFG 1085,2065 r0 top value=0
R120 "CRCW04020000Z0EDHP" FP-CRCW04020000Z0EDHP_0402-MFG 1085,2135 r0 top value=0
R121 "CRCW04020000Z0EDHP" FP-CRCW04020000Z0EDHP_0402-MFG 1085,2185 r0 top value="0 (DNP)"
R122 "CRCW04020000Z0EDHP" FP-CRCW04020000Z0EDHP_0402-MFG 1085,870 r0 top locked value="0 (DNP)"
R123 "CRCW04020000Z0EDHP" FP-CRCW04020000Z0EDHP_0402-MFG 1085,920 r0 top locked value=0
R124 "CRCW04020000Z0EDHP" FP-CRCW04020000Z0EDHP_0402-MFG 1085,990 r0 top locked value=0
R125 "CRCW04020000Z0EDHP" FP-CRCW04020000Z0EDHP_0402-MFG 1085,1040 r0 top locked value="0 (DNP)"
R126 "CRCW06030000Z0EA" 0603 1803.55,3521.81 r270 top locked value=0
R127 "CRCW06030000Z0EA" 0603 1865.95,3521.81 r270 top locked value=0
R128 "CRCW06030000Z0EA" 0603 1950.64,4320.67 r90 top locked value=0
R129 "CRCW06030000Z0EA" 0603 1928.35,3521.81 r270 top locked value=0
R130 "CRCW06030000Z0EA" 0603 2015.2,4320.27 r90 top locked value=0
R131 "CRCW060310K0JNEA" 0603 2047.19,3260.11 r270 top locked value=10k
R132 "CRCW06030000Z0EA" 0603 1990.75,3521.81 r270 top locked value=0
R133 "CRCW06032K20JNEA" 0603 2130.34,3378.05 r0 top locked value=2.2k
R134 "CRCW0603270RJNEA" 0603 2179.49,3523.71 r90 top locked value=270
R135 "CRCW060310K0JNEA" 0603 2263.77,3378.05 r0 top locked value=10k
R136 "CRCW060310K0JNEA" 0603 2368.57,3323.1 r90 top locked value=10k
R137 "CRCW060310R0FKEAHP" 0603 2483.93,3924.44 r180 top locked value=10.0
R138 "CRCW060310R0FKEAHP" 0603 2483.93,3862.03 r180 top locked value=10.0
R139 "CRCW060312K0JNEA" 0603 2483.93,3799.63 r0 top locked value=12k
R140 "CRCW06031K00FKEA" 0603 2483.93,4174.05 r180 top locked value=1.00k
R141 "CRCW06030000Z0EA" 0603 2769.37,3820.37 r0 top locked value=0
R142 "CRCW06030000Z0EA" 0603 2883.52,4024.35 r0 top locked value=0
R143 "CRCW04020000Z0ED" 0402 2915.62,2562.74 r0 top locked value=0
R144 "CRCW04020000Z0ED" 0402 2915.62,2622.11 r0 top locked value=0
R145 "CRCW04020000Z0ED" 0402 2915.62,1416.49 r0 top locked value=0
R146 "CRCW04020000Z0ED" 0402 2915.62,1475.86 r0 top locked value=0
R147 "CRCW06030000Z0EA" 0603 2991.27,2423.85 r0 top locked value=0
R148 "CRCW06030000Z0EA" 0603 2991.27,1277.59 r0 top locked value=0
R149 "CRCW04020000Z0ED" 0402 2999.14,2480.19 r0 top locked value=0
R150 "CRCW04020000Z0ED" 0402 2999.15,1333.94 r0 top locked value=0
R151 "CRCW060310K0JNEA" 0603 3041.57,3409.86 r90 top locked value=10k
R152 "CRCW060310K0JNEA" 0603 3041.57,3875.62 r90 top locked value=10k
R154 "CRCW04020000Z0ED" 0402 3102.29,2480.19 r0 top locked value=0
R155 "CRCW04020000Z0ED" 0402 3102.29,1333.94 r0 top locked value=0
R156 "CRCW060310K0JNEA" 0603 3171.8,3875.62 r90 top locked value=10k
R157 "CRCW060310K0JNEA" 0603 3171.8,3409.86 r90 top locked value=10k
R158 "CRCW0402100RFKED" 0402 3175.9,1447.06 r90 top locked value=100
R159 "CRCW0402100RFKED" 0402 3175.9,2593.32 r90 top locked value=100
R161 "CRCW060310K0JNEA" 0603 3302.04,3409.86 r90 top locked value=10k
R162 "CRCW060310K0JNEA" 0603 3302.04,3875.62 r90 top locked value=10k
R163 "CRCW060310K0JNEA" 0603 3432.28,3409.86 r90 top locked value=10k
R164 "CRCW060310K0JNEA" 0603 3432.28,3875.62 r90 top locked value=10k
R165 "CRCW060310K0JNEA" 0603 3562.51,3875.62 r90 top locked value=10k
R166 "CRCW060310K0JNEA" 0603 3562.51,3409.86 r90 top locked value=10k
R167 "KRL2012E-M-R006-F-T5" FP-KRL2012E-M-R006-F-T5_0805-MFG 287,3974.59 r90 top value=6m
R168 "CRCW060310K0JNEA" 0603 -12.82,3906.4 r0 top value=10k
R169 "ERJ-3EKF2552V" RESC1608X55X30LL15T15 189.89,5297 r180 top value=25.5k
R170 "CRCW060310K0JNEA" 0603 -12.82,3836 r0 top value=10k
R171 "ERJ-3EKF4871V" RESC1608X55X30ML15T15 185.95,5225 r0 top value=4.87k
R172 "CRCW060310K0JNEA" 0603 -39.5,4004.34 r0 top value=10k
R173 "CRCW060310K0JNEA" 0603 7.64,4776.71 r180 top value=10k
R174 "CRCW060310K0JNEA" 0603 -12.82,3768 r0 top value=10k
R175 "ERJ-3EKF2872V" RESC1608X55X30ML15T15 -70.89,4891.46 r270 top value=28.7k
R176 "CRCW060310K0JNEA" 0603 148.5,3768 r180 top value=10k
R177 "ERJ-3EKF3323V" RESC1608X55X30ML15T15 1068.77,4664 r180 top value=332k
R178 "ERJ-3EKF4871V" RESC1608X55X30ML15T15 16,4891.46 r270 top value=4.87k
R179 "ERJ-3EKF1023V" RESC1608X55X30LL15T15 1188.61,4664 r180 top value=102k
R180 "ERJ-2GE0R00X" FP-ERJ-2GE0R00X_0402-MFG 585,2279.69 r90 top value=0
R181 "ERJ-2GE0R00X" FP-ERJ-2GE0R00X_0402-MFG 580,1120 r90 top value=0
R500 "RC0603FR-071KL" 0603 2781.05,2594.21 r270 bottom locked value=1.00k
R501 "RC0603FR-071KL" 0603 2781.04,1447.95 r270 bottom locked value=1.00k
R502 "CRCW060310K0JNEA" 0603 278.48,1606.22 r180 bottom locked value=10k
R503 "CRCW060310K0JNEA" 0603 278.69,1667.32 r0 bottom locked value=10k
R504 "CRCW060310K0JNEA" 0603 442.65,228.4 r180 bottom locked value=10k
R505 "CRCW060310K0JNEA" 0603 443.58,290.04 r0 bottom locked value=10k
R508 "CRCW06030000Z0EA" 0603 1421.6,2765.99 r0 bottom locked value=0
R511 "CRCW040213K0FKED" 0402L 1298.91,2889 r90 bottom locked value=13.0k
R513 "RC0603FR-071K21L" 0603 1159.55,1106.76 r180 bottom locked value=1.21k
R514 "RC0603FR-071K21L" 0603 1159.55,802.61 r180 bottom locked value=1.21k
R515 "RC0603FR-071K21L" 0603 1159.55,2253.01 r180 bottom locked value=1.21k
R516 "RC0603FR-071K21L" 0603 1159.55,1948.87 r180 bottom locked value=1.21k
R517 "RC0603FR-071KL" 0603 992.1,296.2 r270 bottom locked value=1.00k
R518 "RC0603FR-071KL" 0603 992.1,143.36 r270 bottom locked value=1.00k
R519 "RMCF0603ZT0R00" 0603 929.57,143.36 r90 bottom locked value=0
R520 "RC0603FR-071KL" 0603 929.57,296.2 r90 bottom locked value=1.00k
R521 "RC0603FR-071KL" 0603 867.3,296.2 r270 bottom locked value=1.00k
R522 "RC0603FR-071KL" 0603 860.28,1634.5 r270 bottom locked value=1.00k
R523 "RC0603FR-071KL" 0603 860.28,1481.66 r270 bottom locked value=1.00k
R524 "RMCF0603ZT0R00" 0603 797.74,1481.66 r90 bottom locked value=0
R525 "RC0603FR-071KL" 0603 797.74,1634.5 r90 bottom locked value=1.00k
R526 "RC0603FR-071KL" 0603 735.47,1634.5 r270 bottom locked value=1.00k
R527 "CRCW060310K0JNEA" 0603 629.68,2781.09 r0 bottom locked value=10k
R528 "CRCW060310K0JNEA" 0603 629.61,2718.69 r0 bottom locked value=10k
R529 "RMCF0603ZT0R00" 0603 554.93,25.21 r180 bottom locked value=0
R530 "CRCW040278K7FKED" 0402 508.75,1785.8 r0 bottom locked value=78.7k
R531 "CRCW040278K7FKED" 0402 508.75,639.55 r0 bottom locked value=78.7k
R532 "CRCW06030000Z0EA" 0603 496.54,3229.56 r0 bottom locked value=0
R533 "CRCW06030000Z0EA" 0603 496.54,3291.96 r180 bottom locked value=0
R534 "RMCF0603ZT0R00" 0603 442.31,1367.21 r180 bottom locked value=0
R535 "RC0603FR-071KL" 0603 459.51,-6.29 r270 bottom locked value=1.00k
R536 "ERJ-2GE0R00X" FP-ERJ-2GE0R00X_0402-MFG 413.66,2212.12 r0 bottom locked value=0
R537 "ERJ-2GE0R00X" FP-ERJ-2GE0R00X_0402-MFG 413.66,1065.87 r0 bottom locked value=0
R538 "RC0603FR-071KL" 0603 409.65,132.57 r270 bottom locked value=1.00k
R539 "CRCW04021K30FKED" 0402 341.43,639.55 r0 bottom locked value=1.30k
R540 "CRCW04021K30FKED" 0402 341.43,1785.8 r0 bottom locked value=1.30k
R541 "RC0603FR-071KL" 0603 347.43,1335.71 r270 bottom locked value=1.00k
R542 "RC0603FR-071KL" 0603 332.43,133.23 r90 bottom locked value=1.00k
R543 "ERJ-2GE0R00X" FP-ERJ-2GE0R00X_0402-MFG 336.88,2212.12 r180 bottom locked value=0
R544 "ERJ-2GE0R00X" FP-ERJ-2GE0R00X_0402-MFG 336.88,1065.87 r180 bottom locked value=0
R545 "RC0603JR-071KL" 0603 317.19,2293 r90 bottom locked value=1.0k
R546 "RC0603JR-071KL" 0603 316.94,1161.18 r90 bottom value=1.0k
R547 "RC0603FR-071KL" 0603 297.83,1470.88 r270 bottom locked value=1.00k
R548 "CRCW06030000Z0EA" 0603 254.61,2576.82 r0 bottom locked value=0
R549 "RC0603FR-071KL" 0603 270.03,133.23 r90 bottom locked value=1.00k
R550 "RC0603FR-071KL" 0603 235.49,1470.88 r90 bottom locked value=1.00k
R551 "CRCW0402200KFKED" 0402L 218.02,1735.81 r0 bottom locked value=200k
R552 "CRCW0402200KFKED" 0402L 218.02,589.55 r0 bottom locked value=200k
R553 "CRCW06030000Z0EA" 0603 143.11,3022.59 r0 bottom locked value=0
R554 "RC0603FR-071KL" 0603 173.09,1470.88 r90 bottom locked value=1.00k
R555 "CRCW040213K0FKED" 0402L 131.92,2709.55 r90 bottom locked value=13.0k
R556 "CRCW06030000Z0EA" 0603 93.15,3132.99 r90 bottom locked value=0
T1 "WBC1-1TLB" FP-WBC1-1TLB_SMT_XFRMR_3MM81_3MM81-MFG 1275.04,2100 r270 top locked
T2 "WBC1-1TLB" FP-WBC1-1TLB_SMT_XFRMR_3MM81_3MM81-MFG 1275,955 r270 top
TP1 "5011" Keystone5011 4.35,3534.76 r0 top locked
TP2 "5010" Keystone5010 20.41,2814.85 r180 top locked
TP3 "5010" Keystone5010 48.49,3310.22 r0 top locked
TP4 "5010" Keystone5010 106,2614 r0 top locked
TP5 "5010" Keystone5010 609,3890 r0 top
TP6 "5010" Keystone5010 927.84,3171.1 r0 top locked
TP7 "5010" Keystone5010 1163.96,2914.49 r0 top locked
TP8 "5011" Keystone5011 1389.18,3121.06 r0 top
TP9 "5011" Keystone5011 2943.03,3018.32 r270 top locked
TP10 "5000" Keystone5000 1466.99,3728.17 r270 top locked
TP11 "5011" Keystone5011 1046.53,4295.33 r90 top
TP12 "5000" Keystone5000 2693.01,3986.84 r270 top locked
TP13 "5011" Keystone5011 1177.4,159.11 r0 top locked
TP14 "5010" Keystone5010 3345.92,4596.65 r0 top locked
U1 "OPA2140AID" D0008A_N 425.08,1760.81 r0 top locked
U2 "OPA2140AID" D0008A_N 425.08,614.55 r0 top locked
U3 "BUF802IRGT" RGT0016C-MFG 386,2081.25 r0 top locked
U4 "BUF802IRGT" RGT0016C-MFG 386,935 r0 top locked
U5 "SN74LVC1G125DBVR" DBV0005A_L 579.5,3620.53 r180 top locked
U6 "SN74LVC1G126DBVR" DBV0005A_N 762.98,3620.53 r0 top locked
U7 "LMH6518SQ_NOPB" RGH0016A-MFG 908.38,2100.94 r270 top locked
U8 "LMH6518SQ_NOPB" RGH0016A-MFG 908.38,954.68 r270 top locked
U9 "TMUX1574PWR" PW0016A_N 1077.7,3935.84 r180 top locked
U10 "SN74LVC1G125DBVR" DBV0005A_L 1080.73,3634.97 r90 top locked
U11 "LSF0102DCUR" DCU0008A_N 1300.91,3708.45 r90 top locked
U12 "TPS7A9401DSC" DSC0010J-MFG 3419.63,4960.96 r270 top
U13 "TPS7A3901DSCR" DSC0010J 2395.1,5023.48 r180 top
U14 "TMUX1574PWR" PW0016A_N 1624.83,4361.51 r180 top locked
